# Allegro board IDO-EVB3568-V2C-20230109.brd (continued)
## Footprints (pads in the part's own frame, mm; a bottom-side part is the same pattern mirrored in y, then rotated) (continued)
M_MINIPCIE_SOCKET_CK
  round 1.143 hole 1.143 unplated: (-12.499,0)
  round 1.651 hole 1.651 unplated: (12.499,0)
  rect 0.508x2.032 smd: 1(11.801,4.1) 2(11.399,-4.1) 3(11.001,4.1) 4(10.599,-4.1) 5(10.201,4.1) 6(9.799,-4.1) 7(9.4,4.1) 8(8.999,-4.1) 9(8.6,4.1) 10(8.199,-4.1) 11(7.8,4.1) 12(7.399,-4.1) 13(7,4.1) 14(6.599,-4.1) 15(6.2,4.1) 16(5.801,-4.1) 17(2.2,4.1) 18(1.801,-4.1) 19(1.399,4.1) 20(1.001,-4.1) 21(0.599,4.1) 22(0.201,-4.1) 23(-0.201,4.1) 24(-0.599,-4.1) 25(-1.001,4.1) 26(-1.399,-4.1) 27(-1.801,4.1) 28(-2.2,-4.1) 29(-2.601,4.1) 30(-3,-4.1) 31(-3.401,4.1) 32(-3.8,-4.1) 33(-4.201,4.1) 34(-4.6,-4.1) 35(-4.999,4.1) 36(-5.4,-4.1) 37(-5.801,4.1) 38(-6.2,-4.1) 39(-6.599,4.1) 40(-7,-4.1) 41(-7.399,4.1) 42(-7.8,-4.1) 43(-8.199,4.1) 44(-8.6,-4.1) 45(-8.999,4.1) 46(-9.4,-4.1) 47(-9.799,4.1) 48(-10.201,-4.1) 49(-10.599,4.1) 50(-11.001,-4.1) 51(-11.399,4.1) 52(-11.801,-4.1)
  rect 2.413x3.302 smd: 55(-14.651,3.5) 56(14.651,3.5)
MTG370_600_VIA
  round 0.95 hole 0.3: (-2.425,0) (-1.715,1.715) (-1.715,-1.715) (0,2.425) (0,-2.425) (1.715,1.715) (1.715,-1.715) (2.425,0) (2.425,0)
  round 6 hole 3.7: 1(0,0)
MTG430_620_SMTSO_M3
  round 6.2 hole 4.3: 1(0,0)
MX125T-S-2A
  rect 0.635x1.6 smd: 1(-0.625,0) 2(0.625,0)
  rect 2.134x3.048 smd: 3(-3.175,-2.9) 4(3.175,-2.9)
MX125T-S-3A
  rect 0.635x1.6 smd: 1(-1.25,0) 2(0,0) 3(1.25,0)
  rect 2.134x3.048 smd: 4(-3.8,-2.9) 5(3.8,-2.9)
PB-SIDE-S-3_5X4_5
  round 0.6 hole 0.6 unplated: (-0.851,0) (0.851,0)
  rect 0.9x1.2 smd: 1(2.301,0) 2(-2.301,0)
  rect 1.15x1.3 smd: 3(1.675,1.55) 4(-1.675,1.55)
PH200-2A
  rect 1.2x1.2 hole 0.8: 1(1,0)
  round 1.2 hole 0.8: 2(-1,0)
PH200-4A
  rect 1.2x1.2 hole 0.8: 1(3,0)
  round 1.2 hole 0.8: 2(1,0) 3(-1,0) 4(-3,0)
PH200-6A
  rect 1.2x1.2 hole 0.8: 1(5,0)
  round 1.2 hole 0.8: 2(3,0) 3(1,0) 4(-1,0) 5(-3,0) 6(-5,0)
PH200-6AW
  rect 1.2x1.2 hole 0.8: 1(5,0)
  round 1.2 hole 0.8: 2(3,0) 3(1,0) 4(-1,0) 5(-3,0) 6(-5,0)
PJ-326A-3P
  round 1 hole 1: (-0.5,2.901) (6.5,2.901)
  rect 2.2x2.2 smd: 1(0,0) 2(3,5.801)
  rect 2.4x2.4 smd: 3(9.7,2.901)
QFN-40_5X5X04P
  rect 0.7x0.2 smd: 1(-2.35,1.8) 2(-2.35,1.4) 3(-2.35,1) 4(-2.35,0.6) 5(-2.35,0.2) 6(-2.35,-0.2) 7(-2.35,-0.6) 8(-2.35,-1) 9(-2.35,-1.4) 10(-2.35,-1.8) 21(2.35,-1.8) 22(2.35,-1.4) 23(2.35,-1) 24(2.35,-0.6) 25(2.35,-0.2) 26(2.35,0.2) 27(2.35,0.6) 28(2.35,1) 29(2.35,1.4) 30(2.35,1.8)
  rect 0.2x0.7 smd: 11(-1.8,-2.35) 12(-1.4,-2.35) 13(-1,-2.35) 14(-0.6,-2.35) 15(-0.2,-2.35) 16(0.2,-2.35) 17(0.6,-2.35) 18(1,-2.35) 19(1.4,-2.35) 20(1.8,-2.35) 31(1.8,2.35) 32(1.4,2.35) 33(1,2.35) 34(0.6,2.35) 35(0.2,2.35) 36(-0.2,2.35) 37(-0.6,2.35) 38(-1,2.35) 39(-1.4,2.35) 40(-1.8,2.35)
  rect 3.2x3.2 smd: 41(0,0)
R0402
  rect 0.55x0.55 smd: 1(-0.45,0) 2(0.45,0)
R0603
  rect 0.65x0.8 smd: 1(-0.725,0) 2(0.725,0)
R0805
  rect 1x1.2 smd: 1(-1,0) 2(1,0)
RJ45-TH_HR911130A
  round 2.997 hole 3.251 unplated: (-5.715,0) (5.715,0)
  round 1.524 hole 0.889: 1(5.715,-8.89) 2(4.445,-6.35) 3(3.175,-8.89) 4(1.905,-6.35) 5(0.635,-8.89) 6(-0.635,-6.35) 7(-1.905,-8.89) 8(-3.175,-6.35) 9(-4.445,-8.89) 10(-5.715,-6.35)
  round 1.651 hole 1.016: 11(6.624,4.9) 12(4.084,4.9) 13(-4.084,4.9) 14(-6.624,4.9)
  round 2.54 hole 1.651: SH1(-7.846,-3.051) SH2(7.846,-3.051)
RN_0402X4
  rect 0.5x0.399 smd: 1(-0.5,0.8) 4(-0.5,-0.8) 5(0.5,-0.8) 8(0.5,0.8)
  rect 0.5x0.3 smd: 2(-0.5,0.25) 3(-0.5,-0.25) 6(0.5,-0.25) 7(0.5,0.25)
SIM-91288-021
  rect 1.829x1.397 smd: C1(-0.351,12.319) C2(-0.351,9.779) C3(-0.351,7.239) C5(-23.322,12.319) C6(-23.322,9.779) C7(-23.322,7.239) CD1(-0.351,-0.051) CD2(-23.322,-0.051)
SMA_DO-214AC
  rect 1.85x1.45 smd: A(1.95,0) C(-1.95,0)
SMAF
  rect 1.43x1.53 smd: A(-1.84,0) C(1.84,0)
SMD1812
  rect 2.032x3.302 smd: 1(-2.159,0) 2(2.159,0)
SOD123
  rect 0.8x0.75 smd: A(1.7,0) C(-1.7,0)
SOD323
  rect 0.9x0.5 smd: A(1.3,0) C(-1.3,0)
SOD523
  rect 0.65x0.5 smd: A(0.9,0) C(-0.9,0)
SOD-123F
  rect 0.94x0.95 smd: A(-1.45,0) C(1.45,0)
SOP16-P127-390X990
  rect 1.905x0.635 smd: 1(0,0) 2(0,-1.27) 3(0,-2.54) 4(0,-3.81) 5(0,-5.08) 6(0,-6.35) 7(0,-7.62) 8(0,-8.89) 9(6.096,-8.89) 10(6.096,-7.62) 11(6.096,-6.35) 12(6.096,-5.08) 13(6.096,-3.81) 14(6.096,-2.54) 15(6.096,-1.27) 16(6.096,0)
SOT23
  rect 1.05x0.65 smd: 1(-1.15,0.95) 2(-1.15,-0.95) 3(1.15,0)
SOT23-5
  rect 1.1x0.6 smd: 1(-1.35,0.95) 2(-1.35,0) 3(-1.35,-0.95) 4(1.35,-0.95) 5(1.35,0.95)
SOT23-6
  rect 1.05x0.6 smd: 1(-1.35,0.95) 2(-1.35,0) 3(-1.35,-0.95) 4(1.35,-0.95) 5(1.35,0) 6(1.35,0.95)
SOT353
  rect 0.95x0.4 smd: 1(-1.1,0.65) 2(-1.1,0) 3(-1.1,-0.65) 4(1.1,-0.65) 5(1.1,0.65)
SOT523
  rect 0.85x0.3 smd: 1(-0.8,0.5) 2(-0.8,-0.5) 3(0.8,0)
SOT563
  rect 0.47x0.26 smd: 1(-0.74,0.5) 2(-0.74,0) 3(-0.74,-0.5) 4(0.74,-0.5) 5(0.74,0) 6(0.74,0.5)
TF-01A
  round 1 hole 1: (-7.2,-10.5) (0.8,-10.5)
  oval 0.7x2.3 smd: 1(0,0.2) 2(-1.1,0.2) 3(-2.2,0.2) 4(-3.3,0.2) 5(-4.4,0.2) 6(-5.5,0.2) 7(-6.6,0.2) 8(-7.7,0.2) 9(-8.8,0.2)
  rect 1.2x1.4 smd: 10(-10,-0.5)
  rect 1.6x1.4 smd: 11(4.6,-0.5)
  rect 1.2x2.2 smd: 12(-10,-10.2) 13(5.5,-10.2)
TSSOP-8
  rect 1.905x0.381 smd: 1(-2.1,0.975) 2(-2.1,0.325) 3(-2.1,-0.325) 4(-2.1,-0.975) 5(2.1,-0.975) 6(2.1,-0.325) 7(2.1,0.325) 8(2.1,0.975)
unnamed
  round 1 smd: 1(0,0)
USB-9AF-DIP_2X
  round 1.118 hole 0.711: 1(-3.5,0) 2(-1,0) 3(1,0) 4(3.5,0) 5(4,1.5) 6(2,1.5) 7(0,1.5) 8(-2,1.5) 9(-4,1.5) 10(-3.5,3.2) 11(-1,3.2) 12(1,3.2) 13(3.5,3.2) 14(4,4.7) 15(2,4.7) 16(0,4.7) 17(-2,4.7) 18(-4,4.7)
  round 2.794 hole 2.362: 19(-6.57,3.68) 20(6.57,3.68) 21(6.57,-2) 22(-6.57,-2)
USB_SMD-TYPE-C-16P
  round 0.711 hole 0.711 unplated: (-2.89,3.65) (2.89,3.65)
  rect 0.3x1.25 smd: A1(-3.35,4.75) A4(-2.6,4.75) A5(-1.25,4.75) A6(-0.25,4.75) A7(0.25,4.75) A8(-1.75,4.75) A9(2.55,4.75) A12(3.35,4.75) B1(3.05,4.75) B4(2.25,4.75) B5(1.75,4.75) B6(0.75,4.75) B7(-0.75,4.75) B8(1.25,4.75) B9(-2.3,4.75) B12(-3.05,4.75)
  oval 1.2x2.5 hole 0.6x1.8: H1(-4.32,4.15) H2(4.32,4.15)
  oval 1x2 hole 0.6x1.5: H3(-4.32,0) H4(4.32,0)
V0402
  rect 0.57x0.62 smd: 1(-0.48,0) 2(0.48,0)
WIFI_44P_12X12
  rect 1.2x0.5 smd: 1(-5.7,4.5) 2(-5.7,3.6) 3(-5.7,2.7) 4(-5.7,1.8) 5(-5.7,0.9) 6(-5.7,0) 7(-5.7,-0.9) 8(-5.7,-1.8) 9(-5.7,-2.7) 10(-5.7,-3.6) 11(-5.7,-4.5) 23(5.7,-4.5) 24(5.7,-3.6) 25(5.7,-2.7) 26(5.7,-1.8) 27(5.7,-0.9) 28(5.7,0) 29(5.7,0.9) 30(5.7,1.8) 31(5.7,2.7) 32(5.7,3.6) 33(5.7,4.5)
  rect 0.5x1.2 smd: 12(-4.5,-5.7) 13(-3.6,-5.7) 14(-2.7,-5.7) 15(-1.8,-5.7) 16(-0.9,-5.7) 17(0,-5.7) 18(0.9,-5.7) 19(1.8,-5.7) 20(2.7,-5.7) 21(3.6,-5.7) 22(4.5,-5.7) 34(4.5,5.7) 35(3.6,5.7) 36(2.7,5.7) 37(1.8,5.7) 38(0.9,5.7) 39(0,5.7) 40(-0.9,5.7) 41(-1.8,5.7) 42(-2.7,5.7) 43(-3.6,5.7) 44(-4.5,5.7)
  round 0.6 smd: 45(-2.7,3.6) 46(-0.9,3.6) 47(0.9,3.6)
XTAL_32X15_2P
  rect 0.85x1.6 smd: 1(-1.25,0) 2(1.25,0)
XTAL_32X25_4P
  rect 1.2x1.3 smd: 1(-0.9,1.2) 2(-0.9,-1.2) 3(0.9,-1.2) 4(0.9,1.2)

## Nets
GND: C3.2 C4.1 C5.1 C6.1 C7.1 C9.1 C10.1 C11.1 C12.1 C14.1 C15.1 C16.1 C18.1 C19.1 C20.1 C21.1 C22.1 C23.1 C25.1 C26.1 C27.1 C28.1 C29.1 C30.1 C31.1 C32.1 C33.2 C34.2 C35.1 C36.2 C37.2 C38.2 C40.2 C42.2 C43.2 C44.1 C45.1 C46.2 C47.2 C48.1 C49.1 C50.1 C51.1 C52.2 C53.2 C54.1 C55.1 C56.1 C57.1 C58.1 C59.1 C60.1 C61.1 C62.1 C63.2 C65.1 C66.1 C67.1 C68.1 C71.1 C73.2 C74.2 C76.2 C77.2 C78.1 C79.1 C80.1 C81.1 C82.1 C83.1 C84.1 C85.1 C86.1 C87.1 C88.1 C89.1 C90.1 C91.1 C93.1 C94.1 C95.1 C96.1 C97.1 C98.1 C99.1 C100.1 C101.1 C102.1 C103.1 C104.1 C105.1 C106.1 C107.1 C109.1 C110.1 C111.1 C112.1 C114.2 C115.1 C116.1 C117.1 C118.1 C119.1 C120.1 C121.1 C122.1 C123.1 C125.1 C126.1 C127.1 C128.1 C129.1 C130.1 C131.1 C132.1 C133.1 C134.1 C135.1 C136.1 C137.1 C138.1 C139.1 C140.1 C141.1 C142.1 C143.1 C144.1 C145.1 C146.1 C147.1 C148.1 C149.1 C150.1 C151.1 C152.1 C153.1 C154.1 C155.1 C156.1 C157.1 C158.1 C159.1 C160.1 C161.1 C162.1 C163.1 C164.2 C165.1 C166.1 C167.1 C168.2 C169.1 C170.1 C171.1 C172.1 C173.1 C174.1 C175.1 C176.2 C177.2 C179.1 C180.1 C181.1 C182.1 C183.2 C184.2 C185.2 C186.2 C188.2 C190.1 C191.1 C192.1 C193.1 C194.1 C195.1 C196.1 C197.1 C198.1 C199.1 C200.1 C201.1 C202.1 C203.1 C204.1 C205.1 C206.1 C208.1 C209.1 C214.1 C215.1 C216.1 C217.1 C218.1 C219.1 C220.1 C221.1 C222.1 C243.1 C244.1 C245.1 C247.1 C248.1 C249.1 C250.1 C251.1 C252.1 C253.1 C254.1 C255.1 C258.1 C259.1 C260.1 C261.1 D2.1(I/O2) D3.3 D3.8 D4.3 D4.8 D5.1(I/O2) D6.1(I/O2) D7.1(I/O2) D8.1(I/O2) D9.1(I/O2) D10.1(I/O2) D12.1(I/O2) D14.3 D14.8 D15.2(I/O1) D16.2(I/O1) D17.3 D17.8 D18.1(I/O2) D19.1(I/O2) D20.1(I/O2) D21.1(I/O2) D22.1(I/O2) D23.1(I/O2) D24.1(I/O2) D25.1(I/O2) D26.1(I/O2) D27.1(I/O2) D28.1(I/O2) D29.1(I/O2) D30.1(I/O2) D31.1(I/O2) D32.1(I/O2) D33.1(I/O2) D34.3 D34.8 D35.3 D35.8 D36.2(I/O1) D37.3 D37.8 D38.2(I/O1) D40.3 D40.8 D41.3 D41.8 D44.2(I/O1) D45.2(I/O1) D46.2(I/O1) D47.2(I/O1) D48.3 D48.8 D49.3 D49.8 D51.3 D51.8 D52.2(I/O1) D53.2(I/O1) D64.2(I/O1) D65.2(I/O1) D71.2(I/O1) D72.2(I/O1) D73.2(I/O1) D74.2(I/O1) D75.2(I/O1) D76.3 D76.8 D77.3 D77.8 D79.2(I/O1) D80.2(I/O1) D81.2 D82.2 D83.2 D84.2 D96.2(I/O1) D97.1(I/O2) D98.3 D98.8 D99.3 D99.8 D100.2(I/O1) D101.2(I/O1) D102.3 D102.8 D103.3 D103.8 D104.3 D104.8 D105.2(I/O1) D106.2(I/O1) D107.3 D107.8 H1.1 H2.1 J2.15(GND1) J2.30(GND2) J2.31(GND3) J2.51(GND4) J2.56(GND5) J2.69(GND6) J2.84(GND7) J2.95(GND8) J2.106(GND9) J2.121(GND10) J2.145(GND11) J2.151(GND12) J2.158(GND13) J2.165(GND14) J2.180(GND15) J2.194(GND16) J2.195(GND17) J2.214(GND18) J2.217(GND19) J2.240(GND20) J2.254(GND21) J2.256(GND22) J2.258(GND23) J2.260(GND24) J2.N1 J2.N2 J2.N3 J2.N4 J3.6(VSS) J3.10(G1) J3.11(G2) J3.12(G3) J3.13(G4) J4.3 J4.4 J4.5 J5.A1(GND1) J5.A12(GND2) J5.B1(GND3) J5.B12(GND4) J5.H1(GND5) J5.H2(GND6) J5.H3(GND7) J5.H4(GND8) J6.4(GND1) J6.7(GND2) J6.13(GND3) J6.16(GND4) J6.19(SHELL1) J6.20(SHELL2) J6.21(SHELL3) J6.22(SHELL4) J7.4 J8.4 J9.4 J11.2 J13.11 J13.16 J13.18 J13.19 J13.22 J13.25 J13.28 J13.31 J13.34 J13.37 J13.41 J13.42 J14.2 J14.5 J14.8 J14.11 J14.14 J14.17 J14.20 J14.21 J14.22 J14.23 J15.11 J15.16 J15.18 J15.19 J15.22 J15.25 J15.28 J15.31 J15.34 J15.37 J15.41 J15.42 J16.5 J16.6 J16.13 J16.14 J19.10 J19.13 J19.16 J19.19 J19.22 J19.25 J19.26 J20.10 J20.13 J20.16 J20.19 J20.22 J20.25 J20.26 J21.1(GND1) J21.3(GND2) J21.4(GND3) J22.10(GND) J23.10(GND) J24.5 J24.6 J24.24 J24.33 J24.34 J25.2 J25.3 J25.4 J26.4(GND#4) J26.9(GND#9) J26.15(GND#15) J26.18(GND#18) J26.21(GND#21) J26.26(GND#26) J26.27(GND#27) J26.29(GND#29) J26.34(GND#34) J26.35(GND#35) J26.37(GND#37) J26.40(GND#40) J26.43(GND#43) J26.50(GND#50) J26.55(GND#55) J26.56(GND#56) J27.1(GND#1) J27.3(GND#3) J27.9(GND#9) J27.15(GND#15) J27.21(GND#21) J27.27(GND#27) J27.33(GND#33) J27.39(GND#39) J27.45(GND#45) J27.51(GND#51) J27.57(GND#57) J27.71(GND#71) J27.73(GND#73) J27.75(GND#75) J27.G1(EHT1) J27.G2(EHT2) J27.G3(G4) J27.G4(G3) J28.4 J28.13 J28.14 J31.6 J31.7 J31.8 L1.3 LED1.2 LED1.4 Q1.2(SOURCE) Q2.2(SOURCE) Q8.2(SOURCE) Q13.2(SOURCE) Q14.2(SOURCE) Q15.2(SOURCE) R2.2 R5.1 R6.1 R9.1 R12.1 R16.1 R28.1 R33.1 R36.1 R41.1 R45.1 R51.1 R60.1 R72.1 R73.2 R79.1 R81.2 R100.1 R101.1 R102.1 R108.1 R118.1 R119.1 R120.1 R173.1 R176.1 R179.1 R201.2 R208.1 R213.2 R219.1 R225.1 R229.1 R233.1 R235.1 R237.1 R239.1 R241.1 R242.1 R245.1 R268.2 R271.1 R273.1 R277.1 R281.1 R284.1 R286.1 R287.1 R289.1 R290.1 R293.1 R345.1 R385.2 R419.1 R421.1 SIM1.C5(GND) SW1.1 SW1.2 SW1.4 SW2.1 SW2.2 SW2.4 U1.3(GND) U2.3(GND) U3.2(GND) U4.2(GND) U5.2(GND) U6.2(GND) U7.2(GND) U8.6(VSS) U8.10(VS_PLL) U8.16(VSS_1) U8.22(VSS-2) U8.25(VS_A) U8.33(VSS_3) U8.37(DIS_REG) U8.40(TEST) U9.2(GND) U10.2(GND) U11.2(PGND1) U11.11(GND1) U11.15(PGND2) U12.2(GND) U13.2(GND) U14.1(O\E\) U14.3(GND) U15.2(GND) U16.2(GND) U17.2(GND) U18.1(GND1) U18.3(GND2) U18.20(GND3) U18.31(GND4) U18.33(GND5) U18.36(GND6) U19.41(E_PAD) U20.41(E_PAD) U21.4(VSS) U22.2(GND) U25.1(O\E\) U25.3(GND) XT1.2 XT1.4 XT2.2 XT2.4 XT3.2 XT3.4 XT4.2 XT4.4
GND_EARTH: C261.2 HOLE1.1 HOLE2.1 HOLE3.1 HOLE4.1 J22.SH1 J22.SH2 J23.SH1 J23.SH2 R419.2
GND_IN: C2.1 C256.1 C257.1 D1.C(I/O1) J1.2 J1.3 J18.1 J18.2 J30.1 J30.2 J32.1 J32.2 L1.2 R2.1
VBAT_RTC: D70.A J25.1
VBAT_WL_1T1R: C118.2 C119.2 C125.2 Q10.3(DRAIN) R202.2 U18.9(VBAT)
VBUSM: R74.1 U8.35(VBUSM)
VCC1V5_DVP: C100.2 C106.2 C107.2 C108.1 C254.2 J19.3 J20.3 R175.2 U16.5(VOUT)
VCC1V8_DVP: C102.2 C103.2 C104.2 C255.2 J19.4 J20.4 Q16.1(GATE) Q17.1(GATE) R156.2 R161.2 R162.2 R166.2 R172.2 U15.5(VOUT)
VCC2V8_DVP: C98.2 C110.2 C111.2 C253.2 J19.1 J19.2 J20.1 J20.2 R177.2 U17.5(VOUT)
VCC3V3_PHY0: C148.2 C149.2 C150.2 C151.2 C152.2 R211.2 R226.2 R230.2 R258.2 U19.11(AVDD33#11) U19.29(DVDD33) U19.40(AVDD33#40)
VCC3V3_PHY1: C172.2 C173.2 C174.2 C175.2 C176.1 R274.2 R278.2 R306.2 U20.11(AVDD33#11) U20.29(DVDD33) U20.40(AVDD33#40)
VCC3V3_SD: C31.2 D2.2(I/O1) J2.210(VCC3V3_SD_OUT) J3.4(VDD)
VCC5V0_M: C26.2 C27.2 C28.2 C29.2 J2.253(VCC5V0_SYS1) J2.255(VCC5V0_SYS2) J2.257(VCC5V0_SYS3) J2.259(VCC5V0_SYS4) R17.2
VCC5V0_USB1: C42.1 D19.2(I/O1) J7.1 U7.1(VOUT)
VCC5V0_USB2: C46.1 D21.2(I/O1) J8.1 U9.1(VOUT)
VCC5V0_USB3: C52.1 D24.2(I/O1) J9.1 U10.1(VOUT)
VCC5V0_USB_HOST1: C38.1 D16.1(I/O2) J6.10(VBUS2) U6.1(VOUT)
VCC5V0_USB_HOST2: C36.1 D15.1(I/O2) J6.1(VBUS1) U5.1(VOUT)
VCC5V0_USB_OTG0: C32.2 C34.1 D7.2(I/O1) J5.A4(VBUS_1) J5.A9(VBUS_2) J5.B4(VBUS_3) J5.B9(VBUS_4) R27.1 U4.1(VOUT)
VCC5V_HDMI_TX: C85.2 D43.C J14.18
VCC5V_SPK: C249.2 C250.2 C251.2 C252.2 R86.2 U11.4(PVDD1) U11.13(PVDD2)
VCC5V_SYS: C8.2 C9.2 C10.2 C11.2 D42.A D43.A L2.2 Q5.1(GATE) R4.2 R7.2 R17.1
VCC12V_DCIN: C256.2 C257.2 F2.1 J1.4 J17.1 J18.5 J18.6 J29.1 J30.5 J30.6 J32.3 J32.4
VCC_1V8: J2.237(VCC_1V8_OUT) Q19.1(GATE) R30.2 R154.2 R155.2 R200.1 R250.1 R298.1 R398.1 R399.1 R408.1 R413.1
VCC_1V8_HUB: C50.2 C60.2 C61.2 C62.2 U8.3(VD18_1) U8.9(VD_PLL) U8.26(VREG18) U8.29(VD18)
VCC_3V3: J2.245(VCC_3V3_OUT) R14.1
VCC_3V3_HUB: C54.2 C55.2 C56.2 C57.2 C58.2 C59.2 R54.2 R55.2 R58.2 R59.1 R61.2 R65.1 R66.2 R76.2 U8.13(VDD33_1) U8.19(VDD33_2) U8.27(VD3_IN) U8.32(VDD33_3) U8.41(VDD33_4)
VCC_3V8: C190.2 C191.2 C192.2 C193.2 C194.2 C195.2 C196.2 C197.2 C198.2 C199.2 C200.2 C201.2 C202.2 C203.2 C204.2 C207.2 C208.2 C209.2 J26.2(VCC3V3#2) J26.24(NC3) J26.39(VCC3V3#39) J26.41(VCC3V3#41) J26.52(VCC3V3#52) L24.2 R342.2 R343.2
VCC_5V: C17.2 C18.2 C19.2 C20.2 C22.2 C23.2 C33.1 C37.1 C40.1 C43.1 C47.1 C53.1 C82.2 C83.2 C88.2 C89.2 C94.2 C177.1 C205.2 C206.2 C244.2 C248.2 J17.3 J24.35 J24.36 J29.3 L3.2 L15.1 L20.1 Q7.1(GATE) Q11.1(GATE) R11.2 R86.1 R133.1 R388.1 U3.4(VIN) U4.5(IN) U5.5(IN) U6.5(IN) U7.5(IN) U9.5(IN) U10.5(IN) U12.6(VIN) U13.6(VIN) U14.5(VCC) U22.4(VIN) U25.5(VCC)
VCC_12V: C3.1 C4.2 C5.2 C6.2 C7.2 C14.2 C15.2 C16.2 L1.4 R1.2 R3.2 U1.1(IN) U2.1(IN)
VCC_EDP_OUT: C245.2 C246.2 J29.2 J29.4 J29.6 Q12.2(SOURCE) R391.2
VCC_EDP_OUT_: C247.2 J28.1 J28.2 Q12.3(DRAIN)
VCC_LEDA_TX0: C86.2 C87.2 D50.C J15.1 J15.2 U13.5(OVP)
VCC_LEDA_TX1: C81.2 C84.2 D39.C J13.1 J13.2 U12.5(OVP)
VCC_LEDK_TX0: J15.9 J15.10 R117.1 R119.2 R120.2
VCC_LEDK_TX1: J13.9 J13.10 R99.1 R101.2 R102.2
VCC_LVDS_OUT: C91.2 C92.2 J17.2 J17.4 J17.6 Q6.2(SOURCE) R134.2
VCC_LVDS_OUT_: C93.2 J16.1 J16.2 J16.3 Q6.3(DRAIN)
VCCA_CODEC: C67.2 C68.2 R85.2 U11.6(VDD1) U11.9(VDD2)
VCCIO_PHY0: C144.2 C145.2 C146.2 R236.2 R238.2 R240.2 R243.2 R246.2 R249.2 R250.2 U19.28(DVDD_RG)
VCCIO_PHY1: C168.1 C169.2 C170.2 R283.2 R285.2 R288.2 R291.2 R294.2 R297.2 R298.2 U20.28(DVDD_RG)
VCCIO_WL: C120.2 C121.2 C122.2 R180.1 R185.1 R200.2 R204.1 U18.22(VDDIO)
VDD3V3_PCIE30: C214.2 C215.2 C216.2 C217.2 C218.2 C219.2 C220.2 C221.2 C222.2 J27.2(3.3V#2) J27.4(3.3V#4) J27.12(3.3V#12) J27.14(3.3V#14) J27.16(3.3V#16) J27.18(3.3V#18) J27.70(3.3V#70) J27.72(3.3V#72) J27.74(3.3V#74) R359.2
VDD10_PHY0: C136.2 C137.2 C138.2 C139.2 C140.2 C141.2 L22.2 U19.3(AVDD10#3) U19.8(AVDD10#8) U19.21(DVDD10) U19.38(AVDD10#38)
VDD10_PHY1: C160.2 C161.2 C162.2 C163.2 C164.1 C165.2 L23.2 U20.3(AVDD10#3) U20.8(AVDD10#8) U20.21(DVDD10) U20.38(AVDD10#38)
VDD_3V3: C21.2 C24.2 C25.2 C79.2 C101.2 C105.2 C109.2 C123.2 C124.2 C243.2 C260.2 D69.A J13.38 J13.39 J15.38 J15.39 J17.5 J28.19 J29.5 J31.1 L4.2 Q3.1(GATE) Q4.1(GATE) Q10.2(SOURCE) R10.1 R15.2 R37.2 R74.2 R76.1 R80.1 R85.1 R92.2 R93.2 R98.1 R103.1 R105.1 R109.2 R111.2 R112.2 R121.1 R132.1 R202.1 R203.2 R258.1 R267.2 R306.1 R326.2 R327.2 R359.1 R384.1 R387.1 R400.1 R401.1 R409.1 R415.1 U15.1(VIN) U16.1(VIN) U17.1(VIN)
VDD_RTC: C181.2 D69.C D70.C U21.8(VDD)
4G_PWREN_H_GPIO0_D5: J2.11(GPIO0_D5_D/SARADC_VIN6) R344.1
4G_RESET_L_GPIO0_D4: J2.9(GPIO0_D4_D/SARADC_VIN5) R337.2
5G_SSRXN: J26.23(UART1_CTS) R423.2
5G_SSRXP: J26.25(UART1_RFR) R422.2
5G_SSTXN: C187.2 J26.31(UART1_DTR)
5G_SSTXP: C189.2 J26.33(UART1_DCD)
BT_REG_ON_H_GPIO1_D4: J2.18(FSPI_D3/FLASH_CS1N/GPIO1_D4_U) R209.1
BT_WAKE_HOST: R199.2 U18.7(BT_HOST_WAKE)
BT_WAKE_HOST_H_GPIO2_C1: J2.228(I2S2_MCLK_M0/ETH0_REFCLKO_25M/U) R199.1
CAM0_PDN_H_GPIO1_D0: J2.10(FSPI_CLK/FLASH_ALE/GPIO1_D0_D) R150.1
CAM0_RST_L__GPIO1_D1: J2.12(FSPI_D0/FLASH_RDY/GPIO1_D1_U) R151.1
CAM1_PDN_H_GPIO1_D2: J2.14(FSPI_D1/FLASH_RDN/GPIO1_D2_U) R164.1
CAM1_RST_L_GPIO1_C7: J2.16(FSPI_D2/FLASH_WPN/GPIO1_C7_D) R165.1
CAM_CLKOUT0: J2.108(REFCLK_OUT/GPIO0_A0_D) R163.1
CAMERA_PWREN: R416.2 U15.3(EN) U16.3(EN) U17.3(EN)
CAMERA_PWREN_GPIO4_D2: J2.13(GPIO4_D2_D/SARADC_VIN7) R416.1
CAN1_RX: J24.18 R310.5
CAN1_RX_M0: J2.154(I2C3_SDA_M0/UART3_RX_M0/CAN1_RX) R310.4
CAN1_TX: J24.17 R310.6
CAN1_TX_M0: J2.156(I2C3_SCL_M0/UART3_TX_M0/CAN1_TX) R310.3
CAN2_RX: D90.C J24.20 R401.2
CAN2_RX_M0: D90.A J2.44(I2C2_SDA_M1/EBC_GDSP/CAN2_RX_M0) R398.2
CAN2_TX: J24.19 Q19.3(DRAIN) R400.2
CAN2_TX_M0: J2.46(I2C2_SCL_M1/EBC_SDSHR/CAN2_TX_M) Q19.2(SOURCE) R399.2
CIF_CLK0: C95.2 D102.5 D102.6 J19.9 R149.2
CIF_CLK1: C97.2 D103.5 D103.6 J20.9 R163.2 R421.2
CIF_CLKOUT_SOC: J2.52(CIF_CLKOUT/EBC_GDCLK/PWM11_IR_M) R149.1
CIF_PDN0: D102.1 D102.10 J19.6 R150.2
CIF_PDN1: D103.1 D103.10 J20.6 R164.2
CIF_RST0: C96.2 J19.5 R151.2 R156.1
CIF_RST1: C99.2 J20.5 R165.2 R166.1
CLK_32K_OUT: J27.68(SUSCLK(32KHZ)(I)(3.3V)) R352.2
CLK_32K_OUT_GPIO0_B0: J2.112(CLK32K_IN/CLK32K_OUT0/PCIE30X2_) R352.1
DM1_: D18.2(I/O1) J7.2 L8.3 R52.2
DM2_: D23.2(I/O1) J8.2 L9.3 R64.2
DM3_: D25.2(I/O1) J9.2 L10.3 R75.2
DM4: J26.36(USB_D-) R340.1
DM_1: D65.1(I/O2) J24.31 R307.2
DP1_: D20.2(I/O1) J7.3 L8.4 R56.2
DP2_: D22.2(I/O1) J8.3 L9.4 R67.2
DP3_: D26.2(I/O1) J9.3 L10.4 R78.2
DP4: J26.38(USB_D+) R341.1
DP_1: D64.1(I/O2) J24.32 R308.2
DRV: U8.42(DRV)
EDP_EN_H_GPIO0_C5: J2.130(PWM6/SPI0_MISO_M0/PCIE30X2_WAKE) R393.2
EDP_ON_: J30.4 Q11.2(SOURCE) R388.2 R389.2
EDP_ON_GPIO0_C3: J2.126(PWM4/VOP_PWM_M0/PCIE30X1_PERSTN) Q11.3(DRAIN) R387.2 R389.1
EDP_PWM7: J2.132(PWM7_IR/SPI0_CS0_M0/PCIE30X2_PE) R390.1 U25.2(A)
EDP_PWM7_: J30.3 R390.2 U25.4(Y)
EDP_TX_AUXN: C235.2 J2.197(EDP_TX_AUXN)
EDP_TX_AUXN_: C235.1 D77.4 D77.7 J28.15 R384.2
EDP_TX_AUXP: C236.2 J2.199(EDP_TX_AUXP)
EDP_TX_AUXP_: C236.1 D77.5 D77.6 J28.16 R385.1
EDP_TX_D0N: C241.2 J2.213(EDP_TX_D0N)
EDP_TX_D0N_: C241.1 D76.1 D76.10 J28.7
EDP_TX_D0P: C242.2 J2.215(EDP_TX_D0P)
EDP_TX_D0P_: C242.1 D76.2 D76.9 J28.8
EDP_TX_D1N: C239.2 J2.209(EDP_TX_D1N)
EDP_TX_D1N_: C239.1 D76.4 D76.7 J28.9
EDP_TX_D1P: C240.2 J2.211(EDP_TX_D1P)
EDP_TX_D1P_: C240.1 D76.5 D76.6 J28.10
EDP_TX_D2N: C237.2 J2.205(EDP_TX_D2N)
EDP_TX_D2N_: C237.1 D77.1 D77.10 J28.11
EDP_TX_D2P: C238.2 J2.207(EDP_TX_D2P)
EDP_TX_D2P_: C238.1 D77.2 D77.9 J28.12
EDP_TX_D3N: C233.2 J2.201(EDP_TX_D3N)
EDP_TX_D3N_: C233.1 D80.1(I/O2) J28.17
EDP_TX_D3P: C234.2 J2.203(EDP_TX_D3P)
EDP_TX_D3P_: C234.1 D79.1(I/O2) J28.18
EXT_EN: J2.249(EXT_EN) R13.1
FE1_1_DM0: R71.1 U8.30(DMU)
FE1_1_DM1: L8.2 R52.1 R307.1 U8.23(DM1)
FE1_1_DM2: L9.2 R64.1 U8.20(DM2)
FE1_1_DM3: L10.2 R75.1 U8.17(DM3)
FE1_1_DM4: R340.2 U8.14(DM4)
FE1_1_DP0: R69.1 U8.31(DPU)
FE1_1_DP1: L8.1 R56.1 R308.1 U8.24(DP1)
FE1_1_DP2: L9.1 R67.1 U8.21(DP2)
FE1_1_DP3: L10.1 R78.1 U8.18(DP3)
FE1_1_DP4: R341.2 U8.15(DP4)
FE1_1_XIN: C49.2 R68.1 U8.12(XIN) XT1.1
FE1_1_XOUT: C51.2 R68.2 U8.11(XOUT) XT1.3
GMAC0_MCLKINOUT: C131.2 J2.230(I2S2_SCLK_TX_M0/GMAC0_MCLKINOUT) R216.1 R219.2
GMAC0_MDC: J2.232(I2S2_LRCK_TX_M0/GMAC0_MDC/UART9) U19.13(MDC)
GMAC0_MDIO: J2.234(I2S2_SDO_M0/GMAC0_MDIO/UART9_CT) R249.1 U19.14(MDIO)
GMAC0_RSTN_GPIO2_D5: J2.77(LCDC_D5/VOP_BT656_D5_M0/SPI2_CS) R248.1
GMAC0_RXCLK: C147.2 J2.223(SDMMC1_D2/GMAC0_RXCLK/UART7_RX_) R256.2
GMAC0_RXD0: J2.222(GMAC0_RXD0/UART1_CTSN_M0/SPI1_M) R252.2
GMAC0_RXD1: J2.224(I2S2_SCLK_RX_M0/GMAC0_RXD1/UART) R253.2
GMAC0_RXD2: J2.219(SDMMC1_D0/GMAC0_RXD2/UART6_RX_M) R254.2
GMAC0_RXD3: J2.221(SDMMC1_D1/GMAC0_RXD3/UART6_TX_M) R255.2
GMAC0_RXDV_CRS: J2.226(I2S2_LRCK_RX_M0/GMAC0_RXDV_CRS/) R257.2
GMAC0_TXCLK: C134.2 J2.229(SDMMC1_CLK/GMAC0_TXCLK/UART9_TX) R234.1
GMAC0_TXCLK_: C135.2 R234.2 U19.20(TXC)
GMAC0_TXD0: J2.216(GMAC0_TXD0/UART1_RX_M0/GPIO2_B3) R224.1
GMAC0_TXD0_: R224.2 U19.18(TXD0)
GMAC0_TXD1: J2.218(GMAC0_TXD1/UART1_TX_M0/GPIO2_B4) R227.1
GMAC0_TXD1_: R227.2 U19.17(TXD1)
GMAC0_TXD2: J2.225(SDMMC1_D3/GMAC0_TXD2/UART7_TX_M) R228.1
GMAC0_TXD2_: R228.2 U19.16(TXD2)
GMAC0_TXD3: J2.227(SDMMC1_CMD/GMAC0_TXD3/UART9_RX_) R231.1
GMAC0_TXD3_: R231.2 U19.15(TXD3)
GMAC0_TXEN: J2.220(GMAC0_TXEN/UART1_RTSN_M0/SPI1_C) R232.1
GMAC0_TXEN_: R232.2 U19.19(TXCTL)
GMAC1_MCLKINOUT_M1: C155.2 J2.54(CIF_CLKIN/EBC_SDCLK/GMAC1_MCLKI) R270.1 R271.2
GMAC1_MDC_M1: J2.48(CIF_HREF/EBC_SDLE/GMAC1_MDC_M1/) U20.13(MDC)
GMAC1_MDIO_M1: J2.50(CIF_VSYNC/EBC_SDOE/GMAC1_MDIO_M) R297.1 U20.14(MDIO)
GMAC1_RSTN_GPIO2_D7: J2.73(LCDC_D7/VOP_BT656_D7_M0/SPI2_MI) R296.1
GMAC1_RXCLK_M1: C171.2 J2.45(CIF_D13/EBC_SDDO13/GMAC1_RXCLK_) R304.2
GMAC1_RXD0_M1: J2.34(CAM_CLKOUT0/EBC_SDCE1/GMAC1_RXD) R300.2
GMAC1_RXD1_M1: J2.36(CAM_CLKOUT1/EBC_SDCE2/GMAC1_RXD) R301.2
GMAC1_RXD2_M1: J2.41(CIF_D11/EBC_SDDO11/GMAC1_RXD2_M) R302.2
GMAC1_RXD3_M1: J2.43(CIF_D12/EBC_SDDO12/GMAC1_RXD3_M) R303.2
GMAC1_RXDV_CRS_M1: J2.38(ISP_PRELIGHT_TRIG/EBC_SDCE3/GMA) R305.2
GMAC1_TXCLK_M1: C158.2 J2.39(CIF_D10/EBC_SDDO10/GMAC1_TXCLK_) R282.1
GMAC1_TXCLK_M1_: C159.2 R282.2 U20.20(TXC)
GMAC1_TXD0_M1: J2.47(CIF_D14/EBC_SDDO14/GMAC1_TXD0_M) R272.1
GMAC1_TXD0_M1_: R272.2 U20.18(TXD0)
GMAC1_TXD1_M1: J2.49(CIF_D15/EBC_SDDO15/GMAC1_TXD1_M) R275.1
GMAC1_TXD1_M1_: R275.2 U20.17(TXD1)
GMAC1_TXD2_M1: J2.35(CIF_D8/EBC_SDDO8/GMAC1_TXD2_M1/) R276.1
GMAC1_TXD2_M1_: R276.2 U20.16(TXD2)
GMAC1_TXD3_M1: J2.37(CIF_D9/EBC_SDDO9/GMAC1_TXD3_M1/) R279.1
GMAC1_TXD3_M1_: R279.2 U20.15(TXD3)
GMAC1_TXEN_M1: J2.32(ISP_FLASHTRIGOUT/EBC_SDCE0/GMAC) R280.1
GMAC1_TXEN_M1_: R280.2 U20.19(TXCTL)
HDMI_TX_CEC_PORT: D44.1(I/O2) J14.13 Q5.3(DRAIN)
HDMI_TX_CLKN: J2.147(HDMI_TX_CLKN) L19.2
HDMI_TX_CLKN_: D41.5 D41.6 J14.12 L19.3
HDMI_TX_CLKP: J2.149(HDMI_TX_CLKP) L19.1
HDMI_TX_CLKP_: D41.4 D41.7 J14.10 L19.4
HDMI_TX_D0N: J2.155(HDMI_TX_D0N) L18.2
HDMI_TX_D0N_: D41.2 D41.9 J14.9 L18.3
HDMI_TX_D0P: J2.153(HDMI_TX_D0P) L18.1
HDMI_TX_D0P_: D41.1 D41.10 J14.7 L18.4
HDMI_TX_D1N: J2.159(HDMI_TX_D1N) L17.2
HDMI_TX_D1N_: D40.5 D40.6 J14.6 L17.3
HDMI_TX_D1P: J2.157(HDMI_TX_D1P) L17.1
HDMI_TX_D1P_: D40.4 D40.7 J14.4 L17.4
HDMI_TX_D2N: J2.163(HDMI_TX_D2N) L16.2
HDMI_TX_D2N_: D40.2 D40.9 J14.3 L16.3
HDMI_TX_D2P: J2.161(HDMI_TX_D2P) L16.1
HDMI_TX_D2P_: D40.1 D40.10 J14.1($PIN0) L16.4
HDMI_TX_HPD_PORT: D46.1(I/O2) J14.19 R107.2 R108.2
HDMI_TX_HPDIN: J2.143(HDMI_TX_HPDIN) R107.1
HDMI_TXDDC_SCL_PORT: D45.1(I/O2) J14.15 Q3.3(DRAIN) R104.1
HDMI_TXDDC_SDA_PORT: D47.1(I/O2) J14.16 Q4.3(DRAIN) R106.2
HDMITX_CEC_M0: J2.89(HDMITX_CEC_M0/SPI3_CS1_M1/GPIO4) Q5.2(SOURCE) R109.1
HOST_WAKE_BT: R394.2 U18.6(BT_WAKE)
HOST_WAKE_BT_H_GPIO1_D3: J2.20(FSPI_CS0N/FLASH_CS0N/GPIO1_D3_U) R394.1
HP_SNS: J2.244(HP_SNS) J10.1(COM) R81.1
HPL_OUT: C72.2 J2.242(HPL_OUT) R84.1
HPR_OUT: C75.2 J2.246(HPR_OUT) R82.1
HUB_RST: C48.2 R53.2 R66.1 U8.34(XRSTJ)
HUB_RST_GPIO1_A4_D: J2.8(I2S1_SCLK_RX_M0/UART4_RX_M0/PDM) R53.1
I2C1_SCL: J2.146(I2C1_SCL/CAN0_TX_M0/PCIE30X1_BU) R311.2
I2C1_SCL_: J24.22 R311.7
I2C1_SDA: J2.148(I2C1_SDA/CAN0_RX_M0/PCIE20_BUTT) R311.1
I2C1_SDA_: J24.21 R311.8
I2C2_SCL_M0: J2.150(I2C2_SCL_M0/SPI0_CLK_M0/PCIE20_) R111.1 R115.1
I2C2_SDA_M0: J2.152(I2C2_SDA_M0/SPI0_MOSI_M0/PCIE20) R112.1 R116.1
I2C3_SCL_M1: J2.74(LCDC_D20/VOP_BT1120_D11/GMAC1_T) R92.1 R96.1
I2C3_SDA_M1: J2.72(LCDC_D21/VOP_BT1120_D12/GMAC1_T) R93.1 R97.1
I2C4_SCL_M0: J2.42(I2C4_SCL_M0/EBC_GDOE/ETH1_REFCL) R152.1 R155.1
I2C4_SDA_M0: J2.40(I2C4_SDA_M0/EBC_VCOM/GMAC1_RXER) R153.1 R154.1
I2C5_SCL-HDMI: J2.93(HDMITX_SCL/I2C5_SCL_M1/GPIO4_C7) Q3.2(SOURCE) R103.2
I2C5_SCL_M0: J2.78(LCDC_D18/VOP_BT1120_D9/GMAC1_RX) Q17.3(DRAIN) R327.1 R328.2
I2C5_SDA-HDMI: J2.91(HDMITX_SDA/I2C5_SDA_M1/GPIO4_D0) Q4.2(SOURCE) R105.2
I2C5_SDA_M0: J2.76(LCDC_D19/VOP_BT1120_D10/GMAC1_R) Q16.3(DRAIN) R326.1 R329.2
I2C_SCL_RTC: R328.1 U21.6(SCL)
I2C_SDA_RTC: R329.1 U21.5(SDA)
LAN0_A+: D57.A(I/O2) D84.4 J22.2(MDI_0+) R223.2
LAN0_A-: D57.C(I/O1) D84.3 J22.3(MDI_0-) R222.2
LAN0_B+: D56.A(I/O2) D84.6 J22.4(MDI_1+) R221.2
LAN0_B-: D56.C(I/O1) D84.1 J22.7(MDI_1-) R220.2
LAN0_C+: D55.A(I/O2) D83.4 J22.5(MDI_2+) R425.2
LAN0_C-: D55.C(I/O1) D83.3 J22.6(MDI_2-) R424.2
LAN0_D+: D54.A(I/O2) D83.6 J22.8(MDI_3+) R215.2
LAN0_D-: D54.C(I/O1) D83.1 J22.9(MDI_3-) R214.2
LAN1_A+: D61.A(I/O2) D82.4 J23.2(MDI_0+) R266.2
LAN1_A-: D61.C(I/O1) D82.3 J23.3(MDI_0-) R265.2
LAN1_B+: D60.A(I/O2) D82.6 J23.4(MDI_1+) R264.2
LAN1_B-: D60.C(I/O1) D82.1 J23.7(MDI_1-) R263.2
LAN1_C+: D59.A(I/O2) D81.4 J23.5(MDI_2+) R262.2
LAN1_C-: D59.C(I/O1) D81.3 J23.6(MDI_2-) R261.2
LAN1_D+: D58.A(I/O2) D81.6 J23.8(MDI_3+) R260.2
LAN1_D-: D58.C(I/O1) D81.1 J23.9(MDI_3-) R259.2
LVDS_EN_GPIO3_A2: J2.65(LCDC_D9/VOP_BT1120_D1/GMAC1_TXD) R137.2
LVDS_ON_: J18.4 Q7.2(SOURCE) R133.2 R135.2
LVDS_ON_GPIO3_A1: J2.67(LCDC_D8/VOP_BT1120_D0/SPI1_CS0_) Q7.3(DRAIN) R132.2 R135.1
LVDS_PWM13: J18.3 R138.2 U14.4(Y)
LVDS_TX0_CLKN: J16.15 R127.2
LVDS_TX0_CLKP: J16.16 R126.2
LVDS_TX0_D0N: J16.7 R122.8
LVDS_TX0_D0P: J16.8 R122.7
LVDS_TX0_D1N: J16.9 R122.6
LVDS_TX0_D1P: J16.10 R122.5
LVDS_TX0_D2N: J16.11 R123.8
LVDS_TX0_D2P: J16.12 R123.7
LVDS_TX0_D3N: J16.17 R123.6
LVDS_TX0_D3P: J16.18 R123.5
MIC1_INN: C66.2 D97.2(I/O1) J2.250(MIC1_INN)
MIC1_INP: C64.2 J2.248(MIC1_INP)
MIPI_CSI_CLK0N: D99.1 D99.10 J19.17 R148.2
MIPI_CSI_CLK0P: D99.2 D99.9 J19.18 R147.2
MIPI_CSI_CLK1N: D105.1(I/O2) J20.17 R158.2
MIPI_CSI_CLK1P: D106.1(I/O2) J20.18 R157.2
MIPI_CSI_D0N: D98.1 D98.10 J19.11 R139.8
MIPI_CSI_D0P: D98.2 D98.9 J19.12 R139.7
MIPI_CSI_D1N: D98.4 D98.7 J19.14 R139.6
MIPI_CSI_D1P: D98.5 D98.6 J19.15 R139.5
MIPI_CSI_D2N: D99.4 D99.7 J19.20 R140.8
MIPI_CSI_D2N_: D104.1 D104.10 J20.11 R141.5
MIPI_CSI_D2P: D99.5 D99.6 J19.21 R140.7
MIPI_CSI_D2P_: D104.2 D104.9 J20.12 R141.6
MIPI_CSI_D3N: D100.1(I/O2) J19.23 R140.6
MIPI_CSI_D3N_: D104.4 D104.7 J20.14 R141.7
MIPI_CSI_D3P: D101.1(I/O2) J19.24 R140.5
MIPI_CSI_D3P_: D104.5 D104.6 J20.15 R141.8
MIPI_CSI_RX_CLK0N: J2.103(MIPI_CSI_RX_CLK0N) R148.1
MIPI_CSI_RX_CLK0P: J2.101(MIPI_CSI_RX_CLK0P) R147.1
MIPI_CSI_RX_CLK1N: J2.99(MIPI_CSI_RX_CLK1N) R158.1
MIPI_CSI_RX_CLK1P: J2.97(MIPI_CSI_RX_CLK1P) R157.1
MIPI_CSI_RX_D0N: J2.119(MIPI_CSI_RX_D0N) R139.1
MIPI_CSI_RX_D0P: J2.117(MIPI_CSI_RX_D0P) R139.2
MIPI_CSI_RX_D1N: J2.115(MIPI_CSI_RX_D1N) R139.3
MIPI_CSI_RX_D1P: J2.113(MIPI_CSI_RX_D1P) R139.4
MIPI_CSI_RX_D2N: J2.111(MIPI_CSI_RX_D2N) R140.1 R141.4
MIPI_CSI_RX_D2P: J2.109(MIPI_CSI_RX_D2P) R140.2 R141.3
MIPI_CSI_RX_D3N: J2.107(MIPI_CSI_RX_D3N) R140.3 R141.2
MIPI_CSI_RX_D3P: J2.105(MIPI_CSI_RX_D3P) R140.4 R141.1
MIPI_DSI_TX0_CLKN: D51.2 D51.9 J2.133(MIPI_DSI_TX0_CLKN/LVDS_TX0_CLKN) J15.27 R127.1
MIPI_DSI_TX0_CLKP: D51.1 D51.10 J2.131(MIPI_DSI_TX0_CLKP/LVDS_TX0_CLKP) J15.26 R126.1
MIPI_DSI_TX0_D0N: D53.1(I/O2) J2.141(MIPI_DSI_TX0_D0N/LVDS_TX0_D0N) J15.33 R122.1
MIPI_DSI_TX0_D0P: D52.1(I/O2) J2.139(MIPI_DSI_TX0_D0P/LVDS_TX0_D0P) J15.32 R122.2
MIPI_DSI_TX0_D1N: D51.5 D51.6 J2.137(MIPI_DSI_TX0_D1N/LVDS_TX0_D1N) J15.30 R122.3
MIPI_DSI_TX0_D1P: D51.4 D51.7 J2.135(MIPI_DSI_TX0_D1P/LVDS_TX0_D1P) J15.29 R122.4
MIPI_DSI_TX0_D2N: D49.5 D49.6 J2.129(MIPI_DSI_TX0_D2N/LVDS_TX0_D2N) J15.24 R123.1
MIPI_DSI_TX0_D2P: D49.4 D49.7 J2.127(MIPI_DSI_TX0_D2P/LVDS_TX0_D2P) J15.23 R123.2
MIPI_DSI_TX0_D3N: D49.2 D49.9 J2.125(MIPI_DSI_TX0_D3N/LVDS_TX0_D3N) J15.21 R123.3
MIPI_DSI_TX0_D3P: D49.1 D49.10 J2.123(MIPI_DSI_TX0_D3P/LVDS_TX0_D3P) J15.20 R123.4
MIPI_DSI_TX0_RST: C90.2 J15.36 R121.2 R417.2
MIPI_DSI_TX0_RST_GPIO4_C3: J2.136(PWM14_M1/SPI3_CLK_M1/CAN1_RX_M1) R417.1
MIPI_DSI_TX1_CLKN: D37.2 D37.9 J2.96(MIPI_DSI_TX1_CLKN) J13.27
MIPI_DSI_TX1_CLKP: D37.1 D37.10 J2.94(MIPI_DSI_TX1_CLKP) J13.26
MIPI_DSI_TX1_D0N: D38.1(I/O2) J2.104(MIPI_DSI_TX1_D0N) J13.33
MIPI_DSI_TX1_D0P: D36.1(I/O2) J2.102(MIPI_DSI_TX1_D0P) J13.32
MIPI_DSI_TX1_D1N: D37.5 D37.6 J2.100(MIPI_DSI_TX1_D1N) J13.30
MIPI_DSI_TX1_D1P: D37.4 D37.7 J2.98(MIPI_DSI_TX1_D1P) J13.29
MIPI_DSI_TX1_D2N: D35.5 D35.6 J2.92(MIPI_DSI_TX1_D2N) J13.24
MIPI_DSI_TX1_D2P: D35.4 D35.7 J2.90(MIPI_DSI_TX1_D2P) J13.23
MIPI_DSI_TX1_D3N: D35.2 D35.9 J2.88(MIPI_DSI_TX1_D3N) J13.21
MIPI_DSI_TX1_D3P: D35.1 D35.10 J2.86(MIPI_DSI_TX1_D3P) J13.20
MIPI_DSI_TX1_RST: C80.2 J13.36 R98.2 R418.2
MIPI_TX0_BL_PWM13: R110.2 R118.2 R138.1 U13.4(EN) U14.2(A)
MIPI_TX1_BL_PWM12: R91.2 R100.2 U12.4(EN)
MIPI_TX1_BL_PWM12_M0: J2.70(LCDC_D22/PWM12_M0/GMAC1_TXEN_M0) R91.1
MIPI_TX1_RST_GPIO2_D4: J2.79(LCDC_D4/VOP_BT656_D4_M0/SPI2_CS)
MIPI_TX1_RST_GPIO2_D6: J2.75(LCDC_D6/VOP_BT656_D6_M0/SPI2_MO) R418.1
NTC_SARADC_VIN3: J2.5(SARADC_VIN3) R312.2
PCIE20_CLKREQN_3V3_L: J27.52(PCIE_CLKREQ#(IO)(3.3V)) R348.2
PCIE20_CLKREQN_M2_3V3_L: J2.2(I2S1_SDO1_M0/I2S1_SDI3_M0/PDM_S) R348.1
PCIE20_PERSTN_3V3_L: J27.50(PCIE_PERST#(I)(3.3V)) R347.2
PCIE20_PERSTN_M2_3V3_L: J2.6(I2S1_SDO3_M0/I2S1_SDI1_M0/PDM_S) R347.1
PCIE20_PRSNT_3V3_L: J27.69(PEDET(NC-PCIE)(GND-SATA)) R382.1
PCIE20_PRSNT_3V3_L_GPIO3_A6: J2.57(LCDC_D13/VOP_BT1120_CLK/GMAC1_T) R382.2
PCIE20_REFCLKN: J2.184(PCIE20_REFCLKN) R360.1
PCIE20_REFCLKN_: J27.53(REFCLKN) R360.2
PCIE20_REFCLKP: J2.182(PCIE20_REFCLKP) R361.1
PCIE20_REFCLKP_: J27.55(REFCLKP) R361.2
PCIE20_RXN: J2.188(PCIE20_RXN/SATA2_RXN/QSGMII_RXN) R355.1
PCIE20_RXN_: J27.41(PETN0/SATA-B+) R355.2
PCIE20_RXP: J2.186(PCIE20_RXP/SATA2_RXP/QSGMII_RXP) R356.1
PCIE20_RXP_: J27.43(PETP0/SATA-B-) R356.2
PCIE20_TX_N: C212.2 R357.1
PCIE20_TX_P: C213.2 R358.1
PCIE20_TXN: C212.1 J2.192(PCIE20_TXN/SATA2_TXN/QSGMII_TXN)
PCIE20_TXN_: J27.47(PERN0/SATA-A-) R357.2
PCIE20_TXP: C213.1 J2.190(PCIE20_TXP/SATA2_TXP/QSGMII_TXP)
PCIE20_TXP_: J27.49(PERP0/SATA-A+) R358.2
PCIE20_WAKEN_3V3_L: J27.54(PCIE_PEWAKE#(IO)(3.3V)) R349.2
PCIE20_WAKEN_M2_3V3_L: J2.4(I2S1_SDO2_M0/I2S1_SDI2_M0/PDM_S) R349.1
PHY0_CLKOUT125: R216.2 U19.35(CLKOUT)
PHY0_G_LED-: J22.12(G_LED-) R213.1
PHY0_LED0/CFG_EXT: R225.2 R226.1 U19.32(LED0/CFG_EXT)
PHY0_LED1/CFG_LDO0: C133.2 J22.11(G_LED+) R233.2 U19.33(LED1/CFG_LDO0)
PHY0_LED2/CFG_LDO1: C132.2 J22.13(Y_LED-) R229.2 R230.1 U19.34(LED2/CFG_LDO1)
PHY0_MDI0+: R223.1 U19.1(MDI[0]+)
PHY0_MDI0-: R222.1 U19.2(MDI[0]-)
PHY0_MDI1+: R221.1 U19.4(MDI[1]+)
PHY0_MDI1-: R220.1 U19.5(MDI[1]-)
PHY0_MDI2+: R425.1 U19.6(MDI[2]+)
PHY0_MDI2-: R424.1 U19.7(MDI[2]-)
PHY0_MDI3+: R215.1 U19.9(MDI[3]+)
PHY0_MDI3-: R214.1 U19.10(MDI[3]-)
PHY0_REG_OUT: L22.1 U19.30(REG_OUT)
PHY0_RSTN: C143.2 R248.2 U19.12(PHYRSTB)
PHY0_RXCLK/PHYAD1: R237.2 R238.1 R256.1 U19.27(RXC/PHYAD1)
PHY0_RXD0/RXDLY: R239.2 R240.1 R252.1 U19.25(RXD0/RXDLY)
PHY0_RXD1/TXDLY: R242.2 R243.1 R253.1 U19.24(RXD1/TXDLY)
PHY0_RXD2/PLLOFF: R245.2 R246.1 R254.1 U19.23(RXD2/PLLOFF)
PHY0_RXD3/PHYAD0: R236.1 R255.1 U19.22(RXD3/PHYAD0)
PHY0_RXDV/PHYAD2: R235.2 R257.1 U19.26(RXCTL/PHYAD2)
PHY0_XTALIN: C130.2 U19.36(XTAL_IN) XT3.3
PHY0_XTALOUT: C129.2 U19.37(XTAL_OUT/EXT_CLK) XT3.1
PHY0_Y_LED+: J22.14(Y_LED+) R211.1
PHY1_CLKOUT125: R270.2 U20.35(CLKOUT)
PHY1_G_LED-: J23.12(G_LED-) R268.1
PHY1_LED0/CFG_EXT: R273.2 R274.1 U20.32(LED0/CFG_EXT)
PHY1_LED1/CFG_LDO0: C157.2 J23.11(G_LED+) R281.2 U20.33(LED1/CFG_LDO0)
PHY1_LED2/CFG_LDO1: C156.2 J23.13(Y_LED-) R277.2 R278.1 U20.34(LED2/CFG_LDO1)
PHY1_MDI0+: R266.1 U20.1(MDI[0]+)
PHY1_MDI0-: R265.1 U20.2(MDI[0]-)
PHY1_MDI1+: R264.1 U20.4(MDI[1]+)
PHY1_MDI1-: R263.1 U20.5(MDI[1]-)
PHY1_MDI2+: R262.1 U20.6(MDI[2]+)
PHY1_MDI2-: R261.1 U20.7(MDI[2]-)
PHY1_MDI3+: R260.1 U20.9(MDI[3]+)
PHY1_MDI3-: R259.1 U20.10(MDI[3]-)
PHY1_REG_OUT: L23.1 U20.30(REG_OUT)
PHY1_RSTN: C167.2 R296.2 U20.12(PHYRSTB)
PHY1_RXCLK/PHYAD1: R284.2 R285.1 R304.1 U20.27(RXC/PHYAD1)
PHY1_RXD0/RXDLY: R287.2 R288.1 R300.1 U20.25(RXD0/RXDLY)
PHY1_RXD1/TXDLY: R290.2 R291.1 R301.1 U20.24(RXD1/TXDLY)
PHY1_RXD2/PLLOFF: R293.2 R294.1 R302.1 U20.23(RXD2/PLLOFF)
PHY1_RXD3/PHYAD0: R283.1 R303.1 U20.22(RXD3/PHYAD0)
PHY1_RXDV/PHYAD2: R286.2 R305.1 U20.26(RXCTL/PHYAD2)
PHY1_XTALIN: C153.2 U20.36(XTAL_IN) XT4.3
PHY1_XTALOUT: C154.2 U20.37(XTAL_OUT/EXT_CLK) XT4.1
PHY1_Y_LED+: J23.14(Y_LED+) R267.1
PWM3_IR: J2.124(PWM3_IR/EDP_HPDIN_M1/PCIE30X1_W) R311.3
PWM3_IR_: J24.23 R311.6
PWM13_M1: J2.144(PWM13_M1/SPI3_CS0_M1/SATA0_ACT_) R110.1
PWRON: J24.25 R314.2
RESET: J24.26 R311.5
RK809-CLK32K: J2.247(RK809-CLK32K) R205.1
RK809_PWRON: C259.2 J2.251(RK809_PWRON) R314.1 R412.1
RK809_VDC: J2.252(RK809_VDC) R7.1 R9.2
RSET0: R241.2 U19.39(RSET)
RSET1: R289.2 U20.39(RSET)
RTCIC_32KOUT: R206.1 U21.7(CLKOUT)
SARADC_VIN0_: J24.27 R312.8
SARADC_VIN0_KEY/RECOVERY: C182.2 J2.1(SARADC_VIN0_KEY/RECOVERY) R312.1 R330.1
SARADC_VIN2_: J24.29 R312.6
SARADC_VIN2_HP_HOOK: J2.3(SARADC_VIN2_HP_HOOK) R312.3
SARADC_VIN3_: J24.28 R312.7
SARADC_VIN4: J2.7(SARADC_VIN4) R312.4
SARADC_VIN4_: J24.30 R312.5
SCL_CAM0: D102.2 D102.9 J19.7 R152.2 R159.1
SCL_CAM1: D103.2 D103.9 J20.7 Q17.2(SOURCE) R159.2 R162.1
SDA_CAM0: D102.4 D102.7 J19.8 R153.2 R160.1
SDA_CAM1: D103.4 D103.7 J20.8 Q16.2(SOURCE) R160.2 R161.1
SDMMC0_CLK: J2.206(SDMMC0_CLK/TEST_CLKOUT/UART5_TX) R21.1
SDMMC0_CLK_: C30.2 D4.1 D4.10 J3.5(CLK) R21.2
SDMMC0_CMD: J2.204(SDMMC0_CMD/PWM10_M1/UART5_RX_M0) R20.1
SDMMC0_CMD_: D3.5 D3.6 J3.3(CMD) R20.2
SDMMC0_D0: J2.196(SDMMC0_D0/UART2_TX_M1/UART6_TX_) R22.1
SDMMC0_D0_: D4.2 D4.9 J3.7(DATA0) R22.2
SDMMC0_D1: J2.198(SDMMC0_D1/UART2_RX_M1/UART6_RX_) R23.1
SDMMC0_D1_: D4.4 D4.7 J3.8(DATA1) R23.2
SDMMC0_D2: J2.200(SDMMC0_D2/ARMJTAG_TCK/UART5_CTS) R18.1
SDMMC0_D2_: D3.2 D3.9 J3.1(DATA2) R18.2
SDMMC0_D3: J2.202(SDMMC0_D3/ARMJTAG_TMS/UART5_RTS) R19.1
SDMMC0_D3_: D3.4 D3.7 J3.2(CD/DATA3) R19.2
SDMMC0_DET_: D4.5 D4.6 J3.9(CD) R24.2
SDMMC0_DET_L: J2.208(SDMMC0_DET/SATA_CP_DET/PCIE30X1) R24.1
SDMMC2_CLK_M0: J2.27(CIF_D5/EBC_SDDO5/SDMMC2_CLK_M0/) R187.1
SDMMC2_CMD_M0: J2.25(CIF_D4/EBC_SDDO4/SDMMC2_CMD_M0/) R185.2 R186.1
SDMMC2_D0_M0: J2.17(CIF_D0/EBC_SDDO0/SDMMC2_D0_M0/I) R180.2 R181.1
SDMMC2_D1_M0: J2.19(CIF_D1/EBC_SDDO1/SDMMC2_D1_M0/I) R182.1
SDMMC2_D2_M0: J2.21(CIF_D2/EBC_SDDO2/SDMMC2_D2_M0/I) R183.1
SDMMC2_D3_M0: J2.23(CIF_D3/EBC_SDDO3/SDMMC2_D3_M0/I) R184.1
SPI0_CLK: J24.3 R315.6
SPI0_CLK_M1: J2.81(LCDC_D3/VOP_BT656_D3_M0/SPI0_CL) R315.3
SPI0_CS0: J24.4 R315.5
SPI0_CS0_M1: J2.83(LCDC_D2/VOP_BT656_D2_M0/SPI0_CS) R315.4
SPI0_MISO: J24.2 R315.7
SPI0_MISO_M1: J2.87(LCDC_D0/VOP_BT656_D0_M0/SPI0_MI) R315.2
SPI0_MOSI: J24.1 R315.8
SPI0_MOSI_M1: J2.85(LCDC_D1/VOP_BT656_D1_M0/SPI0_MO) R315.1
SPK_CTL_H_GPIO3_B0: J2.53(LCDC_D15/VOP_BT1120_D6/ETH1_REF) R89.1
SPK_MUTE_H_GPIO3_A7: J2.55(LCDC_D14/VOP_BT1120_D5/GMAC1_RX) R90.1
SYS_LED_GPIO4_C5: J2.142(PWM12_M1/SPI3_MISO_M1/SATA1_ACT) R8.1
SYS_RESETN: J2.235(SYS_RESETN) R311.4
TP0_INT: D48.4 D48.7 J15.5 J31.3 R114.2
TP0_INT_L_GPIO3_A3: J2.63(LCDC_D10/VOP_BT1120_D2/GMAC1_TX) R114.1
TP0_RST: D48.5 D48.6 J15.4 J31.2 R113.2
TP0_RST_L_GPIO3_A4: J2.61(LCDC_D11/VOP_BT1120_D3/GMAC1_RX) R113.1
TP0_SCL: D48.2 D48.9 J15.6 J31.4 R115.2
TP0_SDA: D48.1 D48.10 J15.7 J31.5 R116.2
TP1_INT: D34.2 D34.9 J13.5 R95.2
TP1_INT_L_GPIO3_C0: J2.68(LCDC_D23/PWM13_M0/GMAC1_MCLKINO) R95.1
TP1_RST: D34.1 D34.10 J13.4 R94.2
TP1_RST_L_GPIO3_C1: J2.66(LCDC_HSYNC/VOP_BT1120_D13/SPI1_) R94.1
TP1_SCL: D34.4 D34.7 J13.6 R96.2
TP1_SDA: D34.5 D34.6 J13.7 R97.2
TYPEC_CC1: D8.2(I/O1) D11.C J5.A5(CC1) R38.1
TYPEC_CC2: D9.2(I/O1) D13.C J5.B5(CC2) R40.1
UART0_CTSN: J2.134(HDMITX_CEC_M1/PWM0_M1/UART0_CTS) R310.2
UART0_CTSN_: J24.16 R310.7
UART0_RTSN: J2.128(PWM5/SPI0_CS1_M0/UART0_RTSN/GPI) R310.1
UART0_RTSN_: J24.15 R310.8
UART0_RX: J2.120(PWM1_M0/GPUAVS/UART0_RX/GPIO0_C) R309.3
UART0_RX_: J24.14 R309.6
UART0_TX: J2.122(PWM2_M0/NPUAVS/UART0_TX/MCU_JTA) R309.4
UART0_TX_: J24.13 R309.5
UART2_RX_M0: J2.116(UART2_RX_M0/GPIO_D0_U) R25.1
UART2_TX_M0: J2.118(UART2_TX_M0/GPIO_D1_U) R26.1
UART4_RX: J24.12 R309.7
UART4_RX_M1: J2.82(LCDC_D16/VOP_BT1120_D7/GMAC1_RX) R309.2
UART4_TX: J24.11 R309.8
UART4_TX_M1: J2.80(LCDC_D17/VOP_BT1120_D8/GMAC1_RX) R309.1
UART5_RX: J24.10 R316.6
UART5_RX_M1: J2.62(LCDC_DEN/VOP_BT1120_D15/SPI1_CL) R316.3
UART5_TX: J24.9 R316.5
UART5_TX_M1: J2.64(LCDC_VSYNC/VOP_BT1120_D14/SPI1_) R316.4
UART7_RX: J24.7 R316.8
UART7_RX_M1: J2.58(PWM15_IR_M0/SPDIF_TX_M1/GMAC1_M) R316.1
UART7_TX: J24.8 R316.7
UART7_TX_M1: J2.60(PWM14_M0/VOP_PWM_M1/GMAC1_MDC_M) R316.2
UART8_CTSN_M0: J2.233(SDMMC1_DET/I2C4_SCL_M1/UART8_CT) R201.1 U18.41(UART_RTS_N)
UART8_RTSN_M0: J2.231(SDMMC1_PWREN/I2C4_SDA_M1/UART8_) U18.44(UART_CTS_N)
UART8_RX_M0: J2.238(CLK32K_OUT1/UART8_RX_M0/SPI1_CS) U18.42(UART_TXD)
UART8_TX_M0: J2.236(I2S2_SDI_M0/GMAC0_RXER/UART8_TX) U18.43(UART_RXD)
USB1_PWREN_H_GPIO3_A5: J2.59(LCDC_D12/VOP_BT1120_D4/GMAC1_RX) R57.1
USB2_HOST2_DM: J2.28(USB2_HOST2_DM) L6.2 R42.1
USB2_HOST2_DM_: D14.5 D14.6 J6.2(1D-) L6.3 R42.2
USB2_HOST2_DP: J2.26(USB2_HOST2_DP) L6.1 R43.1
USB2_HOST2_DP_: D14.4 D14.7 J6.3(1D+) L6.4 R43.2
USB2_HOST2_PWREN_H_GPIO0_A6: J2.110(GPU_PWREN/SATA_CP_POD/PCIE30X2_) U5.4(EN)
USB2_HOST3_DM: J2.24(USB2_HOST3_DM) R71.2
USB2_HOST3_DP: J2.22(USB2_HOST3_DP) R69.2
USB2_PWREN_H_GPIO4_C3: J2.138(PWM15_IR_M1/SPI3_MOSI_M1/CAN1_T) R70.1
USB3_HOST1_DM: J2.169(USB3_HOST1_DM) L7.2 R46.1
USB3_HOST1_DM_: D14.2 D14.9 J6.11(2D-) L7.3 R46.2
USB3_HOST1_DP: J2.167(USB3_HOST1_DP) L7.1 R47.1
USB3_HOST1_DP_: D14.1 D14.10 J6.12(2D+) L7.4 R47.2
USB3_HOST1_PWREN_H_GPIO3_A0: J2.71(LCDC_CLK/VOP_BT656_CLK_M0/SPI2_) U6.4(EN)
USB3_HOST1_SSRXN: J2.175(USB3_HOST1_SSRXN/SATA1_RXN/QSGM) R375.1 R423.1
USB3_HOST1_SSRXN_: D17.1 D17.10 J6.14(RX2-) R375.2
USB3_HOST1_SSRXP: J2.177(USB3_HOST1_SSRXP/SATA1_RXP/QSGM) R376.1 R422.1
USB3_HOST1_SSRXP_: D17.2 D17.9 J6.15(RX+) R376.2
USB3_HOST1_SSTXN: C187.1 C290.1 J2.171(USB3_HOST1_SSTXN/SATA1_TXN/QSGM)
USB3_HOST1_SSTXN_: C290.2 D17.4 D17.7 J6.17(TX2-)
USB3_HOST1_SSTXP: C189.1 C291.1 J2.173(USB3_HOST1_SSTXP/SATA1_TXP/QSGM)
USB3_HOST1_SSTXP_: C291.2 D17.5 D17.6 J6.18(TX2+)
USB3_OTG0_DM: J2.189(USB3_OTG0_DM) L5.2 R29.1
USB3_OTG0_DM_: D12.2(I/O1) J5.A7(DM1) J5.B7(DM2) L5.3 R29.2
USB3_OTG0_DP: J2.187(USB3_OTG0_DP) L5.1 R34.1
USB3_OTG0_DP_: D10.2(I/O1) J5.A6(DP1) J5.B6(DP2) L5.4 R34.2
USB3_OTG0_ID: J2.193(USB3_OTG0_ID) Q1.3(DRAIN) R31.2
USB3_OTG0_SSRXN: J2.183(USB3_OTG0_SSRXN/SATA0_RXN) R48.1
USB3_OTG0_SSRXN_: D107.1 D107.10 J6.5(RX1-) R48.2
USB3_OTG0_SSRXP: J2.185(USB3_OTG0_SSRXP/SATA0_RXP) R49.1
USB3_OTG0_SSRXP_: D107.2 D107.9 J6.6(RX1+) R49.2
USB3_OTG0_SSTXN: C39.1 J2.179(USB3_OTG0_SSTXN/SATA0_TXN)
USB3_OTG0_SSTXN_: C39.2 D107.4 D107.7 J6.8(TX1-)
USB3_OTG0_SSTXP: C41.1 J2.181(USB3_OTG0_SSTXP/SATA0_TXP)
USB3_OTG0_SSTXP_: C41.2 D107.5 D107.6 J6.9(TX1+)
USB3_OTG0_VBUSDET: J2.191(USB3_OTG0_VBUSDET) R27.2 R28.2
USB3_PWREN_H_GPIO4_C4: J2.140(EDP_HPDIN_M0/SPDIF_TX_M2/SATA2_) R77.1
USB_OTG_PWREN_H_GPIO0_A5: J2.212(SDMMC0_PWREN/SATA_MP_SWITCH/PCI) R32.1
USIM_CLK: C185.1 D75.1(I/O2) R335.2 SIM1.C3(CLK)
USIM_CLK_: J26.12(USIM_CLK) R335.1
USIM_DATA: C188.1 D73.1(I/O2) R331.1 R334.2 SIM1.C7(DATA)
USIM_DATA_: J26.10(USIM_IO) R334.1
USIM_RST: C184.1 D72.1(I/O2) R332.2 R336.2 SIM1.C2(RESET)
USIM_RST_: J26.14(USIM_RESET) R336.1
USIM_VDD: C183.1 C186.1 D74.1(I/O2) R331.2 R332.1 R333.2 SIM1.C1(VDD)
VOLN: C73.1 D30.2(I/O1) J12.1 L11.2
VOLP: C74.1 D31.2(I/O1) J12.2 L12.2
VORN: C76.1 D32.2(I/O1) J12.3 L13.2
VORP: C77.1 D33.2(I/O1) J12.4 L14.2
WIFI1T1R_CLK: C112.2 R187.2 U18.17(SDIO_DATA_CLK)
WIFI1T1R_CMD: R186.2 U18.16(SDIO_DATA_CMD)
WIFI1T1R_D0: R181.2 U18.18(SDIO_DATA_0)
WIFI1T1R_D1: R182.2 U18.19(SDIO_DATA_1)
WIFI1T1R_D2: R183.2 U18.14(SDIO_DATA_2)
WIFI1T1R_D3: R184.2 U18.15(SDIO_DATA_3)
WIFI1T1R_XTAL_IN: C114.1 U18.10(XTAL_IN) XT2.3
WIFI1T1R_XTAL_OUT: R191.2 U18.11(XTAL_OUT)
WIFI_PWREN_L_GPIO0_B7: J2.114(PWM0-M0/CPUAVS/GPIO0_B7_D) R207.2
WIFI_REG_ON_H_GPIO3_D5: J2.33(CIF_D7/EBC_SDDO7/SDMMC2_PWREN_M) R196.1 R210.1
WIFI_WAKE_HOST_H_GPIO3_D4: J2.29(CIF_D6/EBC_SDDO6/SDMMC2_DET_M0/) U18.13(WL_HOST_WAKE)
WIFIBT_32KIN_1T1R: C126.2 R204.2 R205.2 R206.2 U18.24(LPO)
N17053074: C113.2 C115.2 U18.2(WL_BT_ANT)
N17053234: C113.1 C116.2 J21.2(SIG)
N68563646: C179.2 U21.1(OSCI) XT5.2
N68563661: C180.2 U21.2(OSCO) XT5.1
N69300963: C2.2 D1.A(I/O2) F2.2 L1.1 R1.1
N69811939: C12.2 R3.1 R5.2 U1.5(EN)
N69812073: C1.1 L2.1 U1.2(LX)
N69812091: C1.2 U1.4(BS)
N69812134: C8.1 R4.1 R6.2 U1.6(FB)
N69812831: C13.1 L3.1 U2.2(LX)
N69812843: C17.1 R11.1 R12.2 U2.6(FB)
N69812998: C13.2 U2.4(BS)
N69813915: R13.2 U2.5(EN)
N69814391: L4.1 U3.3(SW)
N69814410: C24.1 R15.1 R16.2 U3.5(FB)
N69814930: R14.2 U3.1(EN)
N69815076: LED1.3 R10.2
N69815079: LED1.1 R8.2
N69817092: D5.2(I/O1) J4.1 R25.2
N69817095: D6.2(I/O1) J4.2 R26.2
N69818339: R58.1 U8.1(OVCB_2)
N69818343: R55.1 U8.7(OVCB_4)
N69818347: R54.1 U8.5(OVCB_3)
N69818991: C44.2 R61.1 U8.39(VD33_OUT)
N69818999: R59.2 U8.48(OVCB_1)
N69819001: R65.2 U8.36(BUS_B)
N69819016: R73.1 U8.28(REXT)
N69819018: C45.2 U8.38(VD5_IN)
N69820056: R45.2 U5.3(OCB)
N69820298: R51.2 U6.3(OCB)
N69820533: R57.2 U7.4(EN)
N69820554: R60.2 U7.3(OCB)
N69820805: R70.2 U9.4(EN)
N69820826: R72.2 U9.3(OCB)
N69821095: R77.2 U10.4(EN)
N69821116: R79.2 U10.3(OCB)
N69821410: R32.2 R36.2 U4.4(EN)
N69821431: R33.2 U4.3(OCB)
N69829177: Q1.1(GATE) Q2.3(DRAIN) R30.1 R31.1 R35.2
N69829182: D11.A D13.A R37.1 R38.2 R39.1 R40.2
N69829189: C35.2 Q2.1(GATE) R35.1 R39.2 R41.2
N69844387: C63.1 R80.2 R83.2
N69844453: C64.1 C65.2 D29.2(I/O1) J11.1 R83.1
N69844782: D27.2(I/O1) J10.2(R) R82.2
N69844789: D28.2(I/O1) J10.3(L) R84.2
N69846177: C72.1 R87.1
N69846180: R87.2 U11.7(INL)
N69846237: C75.1 R88.1
N69846239: R88.2 U11.10(INR)
N69846282: C71.2 U11.8(BYPASS)
N69846442: Q14.3(DRAIN) U11.5(M\U\T\E\)
N69846447: Q15.3(DRAIN) U11.12(S\D\)
N69846810: L11.1 U11.3(VOLN)
N69846813: L12.1 U11.1(VOLP)
N69846816: L13.1 U11.14(VORN)
N69846819: L14.1 U11.16(VORP)
N69847759: D42.C R104.2 R106.1
N69853313: C246.1 Q12.1(GATE) R391.1 R392.1
N69853352: Q13.3(DRAIN) R392.2
N69854514: Q13.1(GATE) R393.1
N69857283: R172.1 R173.2 U15.4(ADJ)
N69857307: C108.2 R175.1 R176.2 U16.4(ADJ)
N69857397: R177.1 R179.2 U17.4(ADJ)
N69863572: C117.2 R191.1 XT2.1
N69863896: R209.2 R210.2 U18.34(BT_RST_N)
N69864199: R208.2 U18.29(VDD_TCXO)
N69864441: R196.2 U18.12(WL_REG_ON)
N69864462: C127.2 C128.2 L21.2 U18.23(VIN_LDO)
N69864477: L21.1 U18.21(VIN_LDO_OUT)
N69866041: C124.1 Q10.1(GATE) R203.1 R207.1
N69873113: C142.2 J22.1(CT1/2/3/4)
N69883193: C166.2 J23.1(CT1/2/3/4)
N69887528: L24.1 U22.3(SW)
N69887530: C207.1 R343.1 R345.2 U22.5(FB)
N69887600: R344.2 U22.1(EN)
N69896427: J26.8(VREG_USIM) R333.1
N69897118: J26.22(PERST_N) R337.1
N69899428: J26.42(LED_WWAN) LED2.2(CATHODE)
N69899460: LED2.1(ANODE) R342.1
N69910248: D71.1(I/O2) R330.2 SW1.3
N69911722: R99.2 U12.3(FB)
N69911786: C78.2 J13.17 R413.2 R415.2
N69912226: D39.A L15.2 U12.1(LX)
N69922645: R117.2 U13.3(FB)
N69922778: D50.A L20.2 U13.1(LX)
N69927169: C92.1 Q6.1(GATE) R134.1 R136.1
N69927197: Q8.3(DRAIN) R136.2
N69927388: Q8.1(GATE) R137.1
N70033042: Q15.1(GATE) R89.2
N70033056: Q14.1(GATE) R90.2
N70059784: C258.2 J15.17 R408.2 R409.2
N70064377: D96.1(I/O2) R412.2 SW2.3

Pads without a net: D3 1 10; D81 5; D82 5; D83 5; D84 5; J1 5 6; J2 160 162 164 166 168 170 172 174 176 178 239 241 243; J5 A8 B8; J13 3 8 12 13 14 15 35 40; J15 3 8 12 13 14 15 35 40; J16 4 19 20; J20 20 21 23 24; J26 1 3 5 6 7 11 13 16 17 19 20 28 30 32 44 45 46 47 48 49 51; J27 5 6 7 8 10 11 13 17 19 20 22 23 24 25 26 28 29 30 31 32 34 35 36 37 38 40 42 44 46 48 56 58 67; J28 3 5 6 20; MARK1 1; MARK2 1; MARK3 1; MARK4 1; MARK* 1; MARK*#2 1; SIM1 C6 CD1 CD2; U8 2 4 8 43 44 45 46 47; U18 4 5 8 25 26 27 28 30 32 35 37 38 39 40 45 46 47; U19 31; U20 31; U21 3

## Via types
v1: diameter 0.55, hole 0.3, TOP to BOTTOM, 1878 vias
v2: diameter 0.45, hole 0.2, TOP to BOTTOM, 44 vias

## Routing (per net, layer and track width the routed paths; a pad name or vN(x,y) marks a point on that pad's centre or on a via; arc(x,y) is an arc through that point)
GND: length 4370.9
  TOP w0.127: v1(73.03,63.58) 73.03,64.26 73.99,65.23 75.96,65.23 C158.1 ; v1(95.71,28.22) 96.09,28.6 102.94,28.6 103.71,27.83 103.71,27.67 103.42,27.38 103.42,26.97 103.47,26.92 103.47,26.06 103.84,25.7 103.84,25.48 v1(104.06,25.26) ; J3.12 111.8,82.91 112.73,81.99 112.73,74.42 113.51,73.63 113.87,73.63 114.86,72.64 114.86,68.5 114.33,67.97 114.33,66.5 114.1,66.27 v1(114.1,66.12) ; D105.2 38.38,11.81 39.12,11.07 39.12,9.97 v1(39.46,9.63) ; 60.2,49.81 v1(60.22,49.81) 60.22,49.68 59.99,49.45 58.62,49.45 v1(58.12,48.95) 57.81,48.95 56.69,50.06 56.41,50.06 54.46,48.11 54.46,46.98 55.13,46.31 55.13,44.11 54.84,43.81 54.84,43.76 v1(54.79,43.71) ; v1(94.64,47.04) 94.69,46.99 94.69,46.3 ; 48.74,26.9 48.74,26.77 48.58,26.61 ; 48.74,26.9 v1(48.89,26.75) 48.76,26.61 48.58,26.61 ; 48.74,26.9 48.74,45.92 46.18,48.49 46.18,50.5 45.8,50.88 v1(45.8,51.36) ; v1(109.88,25.6) 110.08,25.81 110.08,28.88 108.03,30.94 97.13,30.94 96.62,31.45 96.62,43.74 97.1,44.22 97.1,46.3 96.85,46.56 94.95,46.56 94.69,46.3 ; v1(72.06,63.7) 72.06,64.06 74.12,66.12 76.98,66.12 C159.1 ; U21.4 78.72,34.1 78.69,34.14 78.69,35.08 78.49,35.28 76.58,35.28 76.3,35 76.3,33.25 76.15,33.1 76.15,31.72 v1(76.02,31.6) 76,31.57 75.77,31.57 75.46,31.27 75.46,28.96 75.77,28.65 78.77,28.65 79.27,29.16 79.27,31.24 v1(78.69,31.83) 78.69,34.01 ; v1(42.34,22.53) 42.34,22.5 42.49,22.35 43.05,22.35 43.26,22.56 46.56,22.56 47.7,23.7 47.7,25.73 48.58,26.61 ; 94.69,46.3 94.56,46.18 94.56,45.42 94.36,45.22 94.36,44.93 94.31,44.88 94.31,44.37 94.97,43.71 94.97,30.95 95.36,30.56 95.36,30.34 96.31,29.39 105.68,29.39 106.38,28.69 106.38,25.63 v1(106.1,25.35) ; v1(67.03,65.2) 67.44,65.2 67.54,65.3 69.06,65.3 C12.1 ; D25.1 102.28,6.84 101.93,7.19 101.93,8.23 102.34,8.64 102.34,11.28 v1(102.06,11.56) ; v1(72.44,70.03) 72.44,70.43 72.67,70.66 73.92,70.66 74.26,70.32 74.26,69.08 71.83,66.65 71.62,66.65 ; C97.1 56.4,50.77 53.95,48.32 53.95,46.77 54.58,46.14 54.58,44.6 53.96,43.97 53.96,43.95 53.95,43.94 53.95,42.88 53.95,42.5 53.29,41.84 53.29,39.45 52.02,38.18 52.02,31.45 52.78,30.68 52.78,21.67 ; 52.78,21.67 52.02,20.9 52.02,20.46 51.83,20.27 51.7,20.4 49.48,20.4 v1(49.4,20.32) ; 52.78,21.67 52.78,20.02 52.53,19.76 v1(52.53,19.63) v1(52.53,19.02) 52.53,17.86 52.4,17.73 52.4,16.97 ; 77.01,67.79 76.86,67.64 C259.1 ; v1(128.6,51.23) 129.62,52.25 129.62,54.94 130.53,55.85 131.75,55.85 132.28,55.32 132.28,54.43 131.01,53.16 J24.5 128.73,49.99 v1(128.6,49.99) ; 52.53,17.09 52.4,16.97 ; 52.4,16.97 v1(52.4,16.94) ; v1(47.96,20.32) 49.05,21.41 51.13,21.41 52.27,22.56 52.27,23.06 v1(52.04,23.29) 52.27,23.52 52.27,24.03 v1(52.04,24.26) 52.27,24.49 52.27,30.43 51.51,31.19 51.51,38.43 52.78,39.7 52.78,42.05 53.44,42.71 53.44,43.09 53.44,43.09 53.44,44.15 53.45,44.16 53.45,44.18 54.08,44.81 54.08,45.93 53.44,46.56 53.44,48.54 56.56,51.66 v1(57.07,51.66) ; v2(51.51,54.56) 51.46,54.51 50.44,54.51 50.29,54.66 50.29,55.4 51,56.11 51.92,56.11 52.48,55.55 v1(52.48,55.32) 53.21,54.58 v1(54.99,54.58) 55.83,54.58 v1(56.26,55.02) 56.72,55.47 v1(56.72,55.5) ; v1(77.11,50.18) 77.29,50 77.29,45.92 77.67,45.54 77.67,44.15 81.48,40.34 81.48,35.51 81.61,35.38 81.61,28.02 81.36,27.76 v1(81.36,27.38) 81.36,27 80.44,26.09 79.78,26.09 79.5,26.37 79.5,26.82 79.88,27.2 v1(80.34,27.2) 80.59,27.46 80.59,27.76 81.1,28.27 81.1,35.13 80.98,35.26 80.98,40.08 77.17,43.89 77.17,45.29 76.78,45.67 76.78,48.59 76.5,48.87 76.05,48.87 75.9,48.72 75.26,48.72 72.85,51.13 v1(72.85,51.77) ; 100.79,49.23 101.68,49.23 102.31,48.59 102.69,48.59 103.45,47.83 v1(104.22,47.83) ; v1(38.68,16.97) 39.62,16.97 40.08,16.51 40.08,14.4 v1(40.47,14.01) 40.63,14.01 42.37,12.27 v1(42.37,9.73) ; v2(76.99,72.09) 76.86,71.96 76.86,71.22 76.96,71.12 v2(76.96,71.12) 76.96,71.12 77.01,71.07 ; v1(34.44,50.85) 35.2,50.85 37.49,48.56 40.44,48.56 40.87,48.13 v1(40.87,47.83) ; D106.2 36.72,10.9 38.04,10.9 38.31,10.63 38.31,10.12 37.96,9.76 J20.19 ; v1(107.19,25.68) 107.16,25.7 107.16,28.63 105.87,29.92 97.31,29.92 96.5,29.92 95.87,30.55 95.87,30.77 95.48,31.16 95.48,31.41 95.55,31.48 95.55,31.69 95.55,44.58 95.05,45.09 95.05,45.21 v1(94.93,45.33) ; v1(86.46,53.42) 86.46,51.66 83.96,49.17 83.96,42.81 84.79,41.99 84.79,37.8 85.29,37.29 85.29,36.25 85.7,35.84 v1(85.7,35.81) 85.29,35.41 84.81,35.41 84.48,35.74 84.48,36.09 84.79,36.4 84.79,37.03 84.28,37.54 84.28,41.73 83.46,42.55 83.46,49.42 85.27,51.23 v1(85.27,51.54) ; v1(116,59.97) 115.82,59.97 115.65,60.15 115.01,60.15 114.63,59.77 v1(114.63,59.66) ; C167.1 53.8,41.5 53.8,39.21 52.55,37.96 52.55,37.94 52.53,37.92 52.53,31.7 53.29,30.94 53.29,28.88 v1(53.52,28.65) 53.29,28.42 53.29,18.03 v1(53.42,17.91) ; 129.57,60.73 128.85,60.02 v1(128.6,60.02) ; v1(30.96,46.94) 30.61,47.29 30.61,47.62 31.27,48.29 v1(32.92,48.29) ; v1(40.89,46.81) 40.89,47.14 40.49,47.55 39.6,47.55 39.09,48.06 37.24,48.06 35.41,49.89 v1(34.44,49.89) ; v1(94.13,30.05) 94.11,30.07 94.11,43.43 93.24,44.29 v1(93.24,44.6) ; v1(67.44,75.62) 67.31,75.74 66.45,75.74 66.23,75.95 65.98,75.95 65.27,76.66 65.23,76.66 D44.2 ; C95.1 76.09,50.67 75.01,50.67 v1(73.89,51.79) ; 113.36,82.8 113.23,82.68 113.23,74.68 113.77,74.14 114.12,74.14 115.39,72.87 115.39,68.25 114.86,67.72 114.86,66.32 115.11,66.07 v1(115.11,65.79)
  TOP w0.152: 77.01,71.07 77.01,67.79
  TOP w0.203: 14.78,50.22 14.14,50.22 13.59,49.67 13.17,49.67 H2.1 ; 14.78,50.22 14.78,47.44 14.96,47.27 14.96,37.69 16.08,36.58 16.08,36.58 16.08,34.44 18.69,31.83 22.94,31.83 24.46,30.3 24.66,30.1 25.22,30.1 25.35,29.97 25.35,29.41 27.89,26.87 33.66,26.87 v1(34.8,25.73) ; 14.78,50.22 16.36,51.79 20.37,51.79 20.37,52.7 J2.254 ; v1(131.39,65.48) 130.89,64.97 130.89,60.64 128.75,58.5 128.74,58.5 128.57,58.33 v1(128.57,58.22) ; XT1.4 114.51,33.92 v1(114.51,34.54) ; v1(114.51,34.54) 113.36,34.54 113.16,34.75 v1(112.09,34.75) ; v1(114.51,34.54) 115.59,34.54 115.79,34.34 115.79,30.45 115.52,30.18 v1(113.49,30.18) ; XT4.4 69.7,41.65 69.7,39.47 69.47,39.24 67.9,39.24 XT4.2 ; C25.1 37.23,25.92 37.8,26.49 37.8,27.05 37.69,27.15 v1(37.8,27.25) 37.8,27.51 35.89,29.41 28.73,29.41 28.73,29.44 28.71,29.44 27.79,30.36 27.79,31.84 27.11,32.51 25.63,32.51 23.77,34.37 19.99,34.37 v1(19.86,34.49) 19.1,35.26 19.1,45.25 ; J2.258 19.92,54.58 20.13,54.79 20.73,54.79 v1(20.83,54.69) v1(20.83,55.24) ; v1(42.49,40.59) 42.62,40.46 v1(43.38,40.46) 45.97,40.46 46.18,40.67 v1(46.18,43.13) 46.18,44.27 45.65,44.8 42.76,44.8 42.37,44.4 42.37,44.21 C129.1 ; v1(116,59.97) 116,59.36 115.52,58.88 115.52,58.27 115.16,57.91 115.16,54.97 115.27,54.86 115.27,54.79 ; v1(73.74,60.27) 73.67,60.34 J2.51 ; C141.1 36.71,45.36 36.02,46.05 v1(35.76,46.05) ; v1(23.93,56.67) 23.9,56.64 23.9,56.36 23.95,56.31 23.95,56.19 23.85,56.09 23.85,55.79 23.85,55.79 23.85,55.6 v1(23.65,55.4) ; 78.69,34.14 78.69,34.01 ; v1(17.58,42.62) 17.51,42.69 17.51,43.3 17.4,43.4 17.4,43.75 J2.N2 17.35,47 17.35,49.25 17.55,49.45 22.28,49.45 24.42,51.6 J2.240 ; U8.10 108.76,34.52 108.92,34.37 v1(108.92,31.95) 110.25,30.61 C51.1 111.13,30.61 v1(111.2,30.68) 111.33,30.56 111.96,30.56 112.34,30.18 113.48,30.18 ; C49.1 110.5,33.55 110.19,33.86 110.19,36.58 109.98,36.78 v1(108.76,36.78) ; v1(28.88,59.11) 28.78,59 28.78,56.59 v1(29.03,56.34) ; C180.1 78.49,31.63 v1(78.69,31.83) ; J2.158 44.92,52.23 v1(45.8,51.36) ; v1(27.89,58.98) 28.03,58.84 28.03,56.58 v1(27.91,56.46) ; v1(100.15,51.1) 100.41,51.36 v1(100.41,51.77) ; v1(76.02,31.6) 76.05,31.6 76.08,31.63 C179.1 ; C154.1 65.74,43.13 v1(65.81,43.21) 66.24,43.64 v1(68.53,43.64) ; v1(35.64,27.25) 35,27.89 28.32,27.89 26.4,29.81 26.4,30.95 26.19,31.17 25.04,31.17 23.29,32.92 19.3,32.92 17.24,34.97 17.24,36.96 15.95,38.25 15.95,49.72 16.03,49.8 17,50.77 18.1,50.77 21.31,50.77 21.47,50.94 v1(21.47,51.03)
  TOP w0.254: J2.145 48.17,60.37 47.96,60.15 v1(47.45,60.15) ; J2.69 69.17,60.46 69.06,60.35 v1(69.06,60.15) ; U8.10 v1(108.76,36.78) ; v1(43.08,60.25) 43.17,60.34 J2.165 v1(43.17,62.92) ; J2.121 56.17,62.4 56.54,62.76 56.9,62.76 56.92,62.74 v1(56.97,62.74) ; v1(105.71,42.67) 105.71,43.93 U8.33 ; v1(60.07,51.26) 59.92,51.41 J2.106 ; v1(122.53,82.75) 121.82,82.04 R28.1 ; D8.1 v1(129.11,80.57) ; J2.15 82.67,60.58 v1(83.12,60.13) ; R9.1 75.26,77.47 75.39,77.6 75.39,79.73 74.52,80.59 73.96,80.59 73.89,80.67 73.89,81.33 73.74,81.48 ; v1(9.09,45.92) 8.51,46.51 4.6,46.51 4.14,46.05 4.14,42.4 J16.14 4.14,40.56 4.14,34.4 J16.6 ; v1(110.31,44.4) 110.31,44.23 110.06,43.98 U8.25 ; D7.1 123.24,80.39 123.01,80.39 v1(122.89,80.26) ; U8.16 112.21,38.45 v1(112.24,38.48) ; v1(64.47,78.82) 64.41,78.77 64.41,77.55 64.92,77.04 D44.2 ; v1(31.7,54.94) 31.7,54.91 30.92,54.14 J2.214 ; v1(79.71,51.89) 79.32,51.89 78.92,52.29 J2.30 ; 19.1,45.25 J2.N2 ; J2.84 65.42,52.19 v1(65.37,52.14) ; v1(30.28,58.6) 30.02,58.85 30.02,60.25 30.17,60.4 J2.217 ; v1(116.51,40.59) 116.51,40.61 115.52,41.61 112.6,41.61 112.44,41.45 U8.22 ; C117.1 114.32,26.43 113.84,25.96 113.84,24.43 113.23,23.83 v1(112.47,23.83) ; J2.95 v1(62.67,62.64) ; v1(46.05,60.15) 46.42,60.15 46.67,60.4 J2.151 ; J2.56 72.42,52.19 v1(72.85,51.77) ; v1(106.76,36.75) U8.6 ; 35.64,54.58 v1(38.94,54.58)
  TOP w0.305: J14.11 v1(63.75,82.33) ; J20.22 36.46,7.86 v1(36.18,7.58) ; J14.14 v1(65.25,82.35) ; U8.37 102.11,42.45 101.8,42.76 v1(101.8,43) ; v1(86.16,63.94) Q14.2 ; Q15.2 82.85,64.62 82.63,64.83 82.16,64.83 81.71,65.28 v1(81.71,65.76) ; J14.2 v1(59.25,82.36) ; J14.8 v1(62.25,82.3) ; U8.40 103.86,40.95 104.22,40.59 104.22,39.3 v1(106.76,36.75) ; J14.17 66.75,82.2 v1(66.55,82.4) ; J14.5 v1(60.75,82.34)
  TOP w0.381: C57.1 114.95,37.22 114.38,37.8 v1(114,37.8) ; v1(121.06,30.18) 123.15,28.08 123.15,27.25 122.38,27.25 v1(120.6,29.03) ; J20.13 40.96,9.62 v1(40.84,9.73) 40.84,9.83 40.46,10.21 D104.8 D104.3 ; v1(105.49,70.31) 105.02,70.77 105.02,70.83 C31.1 104.1,71.13 v1(104.04,71.07) ; R277.1 66.46,38.2 v1(66.47,38.2) ; XT4.2 66.6,39.76 C153.1 65.34,39.76 65.23,39.65 v1(64.97,39.65) ; J2.N1 86.88,45.35 87.58,46.05 v1(87.58,48.08) ; J2.N1 86.24,45.35 85.42,46.18 v1(85.42,48.11) ; J2.N1 v1(86.6,48.08) ; R242.1 v1(31.09,33.99) ; v1(128.6,57.1) 128.6,57.1 D31.1 ; C56.1 99.32,38.67 v1(98.88,38.23) ; v1(120.29,66.17) 119.71,66.75 118.95,66.75 ; C176.2 62.81,33.88 v1(62.53,33.6) 62.88,33.26 C169.1 C168.2 ; v1(78.71,12.9) 78.56,12.75 D37.3 D37.8 ; v1(114.38,27.25) 114.39,27.24 XT2.4 ; v1(114.38,27.25) C117.1 ; v1(114.38,27.25) 114.38,27.89 114.76,28.27 118.72,28.27 119.1,27.89 119.1,26.5 XT2.2 118.04,24.44 v1(117.3,23.7) C114.2 116.6,23.51 115.27,22.17 113.64,22.17 v1(113.61,22.15) ; v1(24.08,25.22) R16.1 C23.1 24.47,26.54 v1(23.97,26.54) 23.98,26.55 23.98,27.13 24.14,27.29 C22.1 23.67,27.64 23.6,27.57 23.54,27.57 23.23,27.25 v1(22.94,27.25) ; C258.1 19.46,30.33 v1(19.63,30.51) ; v1(124.76,57.61) 124.76,58.01 C76.2 ; C79.1 72.69,15.93 v1(73.1,16.33) ; C190.1 105.99,48.77 v1(106.32,48.44) ; v1(43.38,37.54) 43.21,37.72 C133.1 R233.1 ; C95.1 77.01,50.28 v1(77.11,50.18) ; 28.27,3.78 J25.4 29.67,3.25 29.16,2.74 v1(28.27,2.74) ; v1(108.03,47.83) 107.77,47.57 C62.1 ; C66.1 124.87,63.65 D97.1 124.16,63.7 123.9,63.45 v1(123.44,63.45) ; v1(59.25,82.36) 59.12,82.5 58.5,82.5 58.12,82.12 v1(58.12,77.75) v1(58.12,73.99) ; v1(60.15,13.08) D98.3 D98.8 60.15,10.36 60.02,10.24 v1(60.02,9.72) J19.13 ; J5.A1 131.69,83.97 J5.H1 ; v1(26.03,16.03) 26.16,16.03 26.58,15.61 R120.1 ; v1(54.79,43.71) 54.7,43.63 54.7,43.32 C174.1 54.67,43.28 C167.1 ; J3.11 v1(97.2,77.45) ; J3.11 v1(98.49,76.27) ; J3.11 v1(97.2,75.16) ; C30.1 34,51.08 34.19,51.08 34.42,50.85 v1(34.44,50.85) ; C150.1 29.22,43.73 v1(29.06,43.89) ; v1(24.97,63.07) 25.35,63.45 C135.1 ; v1(132.41,80.66) C32.1 v1(131.62,79.86) ; J13.25 v1(81.04,9.73) ; U18.3 113.12,15.92 v1(113.36,16.15) ; v1(122.63,37.29) 122.56,37.36 C123.1 ; v1(55.83,63.45) 55.73,63.55 55.12,63.55 54.56,64.11 D5.1 D6.1 ; v1(93.14,58.98) 93.14,59.06 93.34,59.26 93.34,60.53 93.25,60.62 J26.55 91.96,59.56 v1(91.54,59.56) ; J25.3 24.71,3.78 ; J25.3 23.32,3 23.59,2.73 v1(24.7,2.73) ; J25.3 23.32,4.52 23.7,4.9 ; v1(81.36,20.55) 81.92,21.11 C82.1 C83.1 R100.1 ; C90.1 22.56,45.19 v1(22.3,45.44) 22.31,45.45 22.31,45.99 v1(22.23,46.08) ; D106.2 35.38,13.87 v1(35.03,14.22) 37.39,16.59 38.3,16.59 v1(38.68,16.97) ; v1(97.74,43.26) 97.99,43.26 98.37,42.88 C45.1 99.26,42.18 v1(99.26,42.01) ; R237.1 v1(34.04,33.99) ; D101.2 53.8,12.65 53.42,13.03 53.42,13.28 v1(53.04,13.67) ; D71.2 121.26,79.83 v1(120.8,80.29) ; J2.180 39.42,54.2 39.04,54.58 v1(38.94,54.58) ; J2.195 35.67,59.93 35.26,59.51 33.93,59.51 v1(33.91,59.54) ; R290.1 v1(55.83,31.45) ; 123.77,20.78 123.77,21.16 v1(123.9,21.29) ; 123.77,20.78 R60.1 ; 123.77,20.78 v1(123.27,21.29) ; C48.1 101.65,47.14 101.44,47.35 v1(100.1,47.35) ; v1(128.6,55.45) D30.1 ; v2(76.99,72.09) 76.43,72.09 D96.2 ; v1(54.69,36.4) 54.74,36.46 C162.1 ; v1(33.78,30.18) 33.98,29.98 C147.1 ; v1(15.21,64.54) 14.81,64.14 14.81,63.92 C4.1 ; C155.1 68.99,38.86 v1(69.15,38.7) 68.17,37.72 R271.1 ; C12.1 69.91,65.67 69.95,65.71 v1(69.98,65.71) 70,65.71 70.05,65.67 R5.1 70.75,65.67 71.34,66.26 71.34,66.37 71.62,66.65 ; v1(85.8,9.83) 85.54,9.57 J13.16 ; v1(79.49,9.69) 79.54,9.64 J13.28 ; v1(29.79,67.79) 29.44,67.44 D84.2 ; v1(26.47,42.82) 26.85,42.44 27.03,42.44 C143.1 ; 51.58,19.63 51.83,19.89 51.83,20.33 ; v1(21.06,44.65) 19.89,44.65 19.19,45.35 J2.N2 ; v1(39.7,30.12) 39.7,30.61 C136.1 39.55,30.74 38.96,30.15 ; C50.1 111.07,47.06 v1(111.07,47.83) ; C68.1 122.32,64.94 v1(122.1,64.72) ; v1(13.44,65.63) 13.44,64.53 C4.1 ; D36.2 77.55,15.57 v1(77.67,15.7) ; R81.2 121.62,74.63 v1(121.36,74.37) ; C61.1 104.54,31.95 v1(104.09,31.95) ; R273.1 66.29,35.59 v1(66.5,35.79) 66.06,36.23 R281.1 ; C77.2 124.98,59.32 v1(124.84,59.18) ; J26.43 v1(99.7,60.1) ; v1(87.83,9.86) 88.04,9.65 J13.11 ; C128.1 v1(97.49,23.7) ; C84.1 v1(94.44,21.58) ; C142.1 33.71,67.44 v1(33.73,67.42) 33.76,67.44 R213.2 ; XT3.2 43.37,40.47 v1(43.38,40.46) ; C60.1 108.73,32.14 v1(108.92,31.95) ; C25.1 C21.1 34.99,25.92 v1(34.8,25.73) ; R287.1 59.11,31.22 C171.1 59.42,32.01 v1(59.61,32.21) ; XT3.4 45.49,43.82 v1(46.18,43.13) ; v1(37.41,32.97) 37.29,33.1 C145.1 C144.1 36.65,32.08 v1(37.03,32.46) ; C54.1 98.27,38.03 v1(98.27,38.4) ; v1(58.45,51.49) 58.54,51.4 58.54,50.86 R421.1 58.42,50.74 57.73,50.74 C97.1 ; v1(94.06,73.48) 94.76,72.78 R45.1 ; v1(113.49,30.18) 113.48,30.18 113.48,30.75 XT1.2 ; v1(26.03,15.16) 25.88,15.16 25.44,15.61 R119.1 ; J5.H2 124.25,83.97 J5.A12 ; J19.10 v1(61.52,9.71) ; v1(122.5,70.18) 122.82,69.86 C249.1 C252.1 ; J13.37 v1(75.04,7.7) ; v1(72.44,70.03) 72.29,70.18 72,70.18 R6.1 ; v1(116.79,74.32) D28.1 ; R293.1 v1(54.81,31.45) ; J13.19 84.04,9.59 v1(84.28,9.83) 84.54,9.57 J13.18 ; v1(100.51,73.43) D3.8 D3.3 ; C104.1 C100.1 47.19,12.14 v1(47.45,12.4) ; v1(27.36,34.04) 26.19,34.04 24.21,36.02 D49.3 D49.8 ; J3.6 v1(107.3,77.17) ; v1(38.99,30.12) 38.96,30.15 ; 38.96,30.15 38.91,30.2 38.91,30.26 C137.1 38.33,30.64 v1(38.33,30.12) ; v1(109.17,11.76) 109.49,11.44 R201.2 ; C254.1 v1(66.62,13.41) ; C65.1 v1(128.73,62.69) 128.91,62.51 128.91,61.89 C63.2 ; C175.1 61.85,34.14 61.85,33.58 v1(61.87,33.55) ; v1(59.99,78.82) D40.8 D40.3 ; v1(9.42,60.17) 9.42,60.69 L1.3 ; R12.1 23.04,25.68 23.46,25.26 23.46,25.25 v1(23.4,25.19) ; R208.1 v1(99.73,18.66) ; v1(104.55,11.73) 104.06,12.23 U18.36 ; v1(59.66,33.5) 59.79,33.63 R284.1 ; D46.2 69.29,77.98 v1(69.37,77.9) 69.44,77.97 R108.1 ; v1(66.95,45.16) 66.76,45.36 R289.1 C173.1 ; v1(27.37,36.91) 27.34,36.88 26.64,36.88 24.84,38.68 D51.3 D51.8 ; v1(111.8,87.93) J3.12 111.15,86.62 v1(110.8,86.62) ; C59.1 114.95,40.14 114.68,40.41 v1(114.68,40.49) ; J26.27 v1(106.1,62.87) ; v1(124.87,56.34) 124.87,56.99 C74.2 ; J19.19 v1(57.02,9.78) 57.02,10.16 57.23,10.36 D99.8 D99.3 v1(57.23,13.08) ; C248.1 104.85,68.21 104.85,69.39 v1(104.65,69.6) ; v1(29.93,13.91) 29.4,14.44 U14.1 ; D27.1 120.6,74.63 v1(120.35,74.37) ; C98.1 v1(48.21,12.4) ; C58.1 v1(109.8,47.83) ; J26.29 v1(105.3,62.88) ; v1(104.22,47.83) 104.22,47.77 C55.1 ; v1(42.37,9.73) 42.46,9.64 J20.10 ; v1(125.55,23.01) 125.63,22.94 D65.2 ; v1(34.04,54.71) 34.06,54.69 35.54,54.69 35.92,54.31 J2.194 ; C80.1 75.13,13.29 76.28,12.14 76.28,9.98 v1(76.54,9.72) J13.34 ; v1(65.86,13.39) 65.61,13.13 C255.1 ; D35.8 D35.3 v1(81.23,12.9) ; J26.21 108.5,59.87 108.88,59.49 v1(109.47,59.49) ; D103.3 D103.8 v1(43.76,10.13) ; J26.4 118.5,52.19 v1(118.92,51.77) ; v1(111.8,77.33) J3.10 v1(111.8,75.13) ; v1(38.66,15.19) 38.38,14.91 D105.2 ; C4.1 14.43,63.58 13.94,64.06 13.94,64.14 v1(13.46,64.62) ; U25.3 v1(12.27,17.33) ; L1.3 v1(10.05,62.62) ; L1.3 v1(10.05,60.21) ; D34.8 D34.3 v1(92.41,12.78) ; v1(56.21,70.05) 55.06,70.05 54.68,69.67 J4.3 ; C243.1 15.49,11.71 ; 15.49,11.71 v1(17.73,11.71) ; 15.49,11.71 v1(16.43,12.65) ; D14.3 v1(84.63,71.32) ; v1(41.22,42.88) 40.79,43.31 C149.1 ; v1(30.05,33.99) 30.12,34.06 R245.1 ; v1(114.12,16.21) 114.41,15.92 C115.1 115.11,15.92 v1(115.39,16.21) ; v1(100.41,51.77) 100.9,52.26 J26.40 ; v1(79.68,74.22) 79.63,74.17 D107.8 ; v1(114.66,62.94) 114.1,62.38 J26.15 ; J26.26 v1(106.5,55.07) ; v1(61.57,48.95) 61.57,47.68 62.31,46.94 C164.2 ; C44.1 98.58,41.16 v1(98.58,42.01) ; v1(127.97,80.49) D12.1 ; v1(67.08,26.09) 67.08,25.97 67.33,25.72 U17.2 ; D53.2 23.9,41.96 24.51,41.35 v1(25.37,41.35) ; C126.1 v1(97.49,22.68) ; C127.1 97.64,27.36 96.82,27.36 v1(96.8,27.33) 97.4,27.33 97.4,27.15 97.64,27.15 97.82,26.97 97.82,26.86 C122.1 ; v1(42.49,40.59) 42.18,40.9 C130.1 ; C73.2 v1(124.98,54.81) ; v1(29.06,45.19) 30.81,46.94 v1(30.96,46.94) ; v1(55.68,9.75) 55.52,9.6 J19.22 ; C195.1 107.52,49.23 v1(107.9,48.84) ; v1(63.32,10.85) D102.8 D102.3 ; J2.31 78.67,60.49 v1(79.04,60.12) ; J19.16 v1(58.52,9.83) ; C85.1 72.48,77.05 72.52,77.01 73,77.5 v1(73,77.88) ; v1(26.52,43.38) 27.06,43.38 C148.1 ; C134.1 27.1,64.69 26.62,65.18 v1(26.62,65.23) ; v1(40.69,39.52) 40.67,39.52 R229.1 ; v1(125.5,80.48) 125.5,80.7 125.35,80.85 D9.1 ; C181.1 74.76,36.63 v1(74.85,36.73) ; R235.1 v1(33.1,33.99) ; D20.1 126.52,15.22 v1(126.85,15.54) ; v2(84.94,74.17) 84.63,73.86 D14.8 ; D25.1 101.95,6.35 v1(101.27,6.35) ; C151.1 C152.1 v1(36.91,33.99) ; D41.3 D41.8 v1(62.99,78.79) ; C96.1 66.75,15.95 v1(66.62,16.08) ; C217.1 43.19,35.38 v1(42.49,35.38) 42.11,35.38 40.97,36.53 40.97,37.54 40.39,38.13 R225.1 ; C166.1 51.06,67.44 52.13,68.51 J4.5 52.13,71.34 51.66,71.81 ; v1(95.11,25.08) 95.11,24.9 94.93,24.73 R101.1 ; J26.18 109.7,54.26 v1(109.27,54.69) ; D33.1 128.3,59.72 v1(128.6,60.02) ; J3.13 v1(96.3,84.32) ; J3.13 v1(96.3,87.49) ; J3.13 v1(95.16,85.97) ; J13.22 v1(82.54,9.73) ; v1(45.8,38.73) C131.1 ; J13.31 v1(78.04,9.71) ; C49.1 110.89,33.55 v1(112.09,34.75) ; v1(40.84,42.37) R241.1 C139.1 ; v1(70.18,70.03) 69.49,69.34 69.27,69.34 69.17,69.24 68.6,69.24 C7.1 68.52,69.22 68.38,69.07 68.38,67.34 v1(68.36,67.32) ; R239.1 v1(32.08,33.99) ; v1(96.01,14.2) C53.2 v1(96.77,14.92) ; v1(126.17,80.61) D10.1 ; D45.2 66.51,77.03 67.05,77.03 v1(67.06,77.04) 67.13,76.96 67.54,76.96 D47.2 ; C93.1 10.94,33.11 v1(10.26,33.78) ; C202.1 v1(108.66,48.84) ; U18.33 v1(100.03,14.12) ; v1(117.3,16.21) 117.61,15.89 C116.1 118.26,15.89 v1(118.57,16.21) ; R286.1 v1(57.86,33.6) ; D38.2 v1(76.28,15.7) ; C132.1 43.28,38.89 v1(43.36,38.81) ; C172.1 67.01,32.01 v1(67.01,31.95) 67.01,31 66.62,30.61 C160.1 65.66,30.61 v1(65.61,30.66) 65.56,30.61 C161.1 64.53,30.61 v1(64.21,30.94) ; C99.1 v1(45.92,14.43) ; D26.1 v1(103.73,6.2) ; D23.1 v1(113.08,6.27) ; U18.31 v1(100.06,15.92) ; v1(64.9,74.5) 64.92,74.48 C6.1 ; R179.1 v1(66.12,19.2) ; C120.1 98.74,26.91 98.74,26.98 98.54,27.18 98.47,27.18 98.41,27.24 98.09,27.24 v1(98.02,27.3) ; C253.1 v1(67.64,13.41) ; J26.35 102.9,62.38 v1(102.49,62.79) 102.1,62.4 J26.37 v1(102.1,60.07) ; R176.1 v1(59.89,19.38) ; v1(102.82,71.75) 102.97,71.61 D2.1 ; C209.1 118.06,49.79 C199.1 C200.1 ; D81.2 39.95,67.39 v1(40.34,67.77) ; v1(33.76,4.42) J20.26 v1(33.76,8.31) ; v1(33.91,13.51) 33.88,13.54 33.88,14.72 C94.1 ; U25.1 12.25,18.63 v1(12.4,18.49) ; D82.2 v1(46.81,67.39) ; C156.1 36.3,67.23 v1(36.78,66.75) ; 112.85,71.83 113.67,71.83 114.4,72.57 v1(114.4,72.69) ; C146.1 v1(35,33.99) ; J26.34 103.3,54.43 102.92,54.81 v1(102.31,54.81) ; D107.3 v1(79.63,71.35) ; XT4.4 68.79,43.37 v1(68.53,43.64) ; D4.3 D4.8 v1(107.01,73.48) ; v1(64.39,41.22) 64.39,41.28 64.85,41.73 64.85,41.86 65.55,42.56 C154.1 ; U15.2 v1(56.68,26.11) ; v1(58.12,48.95) 57.76,48.59 C165.1 ; v1(123.44,62.81) 123.44,62.15 122.55,61.26 J26.56 ; D17.3 v1(88.7,71.45) ; C140.1 32.21,45.69 v1(31.85,46.05) ; C121.1 v1(97.49,24.59) ; C129.1 41.46,43.83 v1(41.4,43.89) ; v1(98.04,73.1) D15.2 ; v1(60.76,33.6) C170.1 ; D52.2 23.6,40.56 24.08,40.08 25.65,40.08 v1(25.96,39.78) ; v1(55.12,13.16) 55.07,13.11 D100.2 ; v1(123.6,16) 123.8,16 124.59,15.22 D18.1 ; D32.1 v1(128.57,58.22) ; v1(95.4,8.26) 95.4,7.05 J13.41 95.39,6.39 96.34,7.34 v1(96.34,8.31) ; 118.95,71.83 v1(120.22,71.83) ; C78.1 v1(89.42,12.57) ; C81.1 93.44,17.33 v1(92.79,17.98) ; J26.9 v1(116.5,62.91) ; R102.1 v1(94.26,24.42) ; D17.8 v1(88.7,73.66) ; U18.20 v1(104.06,25.26) ; v1(109.55,64.34) 109.6,64.34 109.86,64.08 C71.1 ; C182.1 v1(122.19,76.91) ; R73.2 v1(108.79,47.83) ; R219.1 v1(45.8,39.83) ; U16.2 v1(61.8,26.14) ; v1(128.73,63.7) D29.1 ; D22.1 v1(114.38,6.3) ; J20.16 v1(39.46,9.63)
  TOP w0.508: U13.2 v1(29.54,17.42) ; 69.42,81.48 69.42,81.48 J14.20 ; v1(112.57,9.86) 112.12,10.31 R72.1 ; v1(26.9,23.13) C89.1 v1(28.02,23.13) C88.1
  TOP w0.61: LED1.2 73.74,84.91 ; LED1.2 73.74,83.13 ; LED1.2 74.63,84.02 ; LED1.2 72.85,84.02
  TOP w0.889: 79.87,75.21 J6.20 81.44,76.79 ; 5.89,33.48 J16.6 4.23,33.48 ; 104.91,3 J9.4 ; J9.4 105.69,3.78 ; J9.4 106.47,3 ; J8.4 117.49,3 ; J8.4 116.71,3.78 ; J8.4 115.93,3 ; J14.22 56,88.62 ; J14.22 56,86.26 ; J14.22 56.78,87.44 ; 133.55,53.3 J24.6 133.55,51.25 ; 133.55,28.39 J24.24 ; J24.24 133.55,30.44 ; J24.24 132.53,29.41 ; 132.29,86 J5.H1 133.06,84.57 ; 127.72,3.78 J7.4 126.95,3 ; 70.5,86.26 J14.23 ; J14.23 70.5,88.62 ; J14.23 71.28,87.44 ; J14.23 69.72,87.44 ; 82.52,15.05 J2.N3 ; J2.N3 85.2,12.38 ; J2.N3 87.88,15.05 ; 79.87,84.04 J6.21 78.29,82.47 ; J6.4 83.67,80.47 ; J6.4 82.2,80.47 ; J6.4 82.94,81.2 ; 4.23,63 J28.14 5.89,63 ; 7.89,33.48 J16.5 6.23,33.48 ; 123.65,87.54 J5.H4 ; J5.H4 122.97,88.72 ; J5.H4 124.32,88.72 ; 36.91,74.88 36.91,75.82 ; 36.91,74.88 37.85,74.88 ; 36.91,74.88 36.91,73.94 ; 132.29,87.54 J5.H3 ; J5.H3 132.96,88.72 ; J5.H3 131.61,88.72 ; 93.01,75.21 J6.19 93.01,78.36 ; 117.54,9.35 H1.1 ; H1.1 119.96,6.92 ; H1.1 119.96,11.78 ; 122.87,84.57 J5.H2 123.65,86 ; J14.21 56.78,81.48 ; J14.21 56,83.16 ; J14.21 56,79.8 ; 132.53,16.71 J24.34 ; J24.34 133.55,17.74 ; J24.34 133.55,15.69 ; J24.33 132.04,16.71 ; J24.33 131.01,15.69 ; J24.33 129.99,16.71 ; 91.43,82.47 J6.22 ; J6.22 94.58,82.47 ; J6.22 93.01,84.04 ; 11.86,45.08 H2.1 ; H2.1 8.58,48.36 ; H2.1 11.86,51.64 ; 90.52,29.68 J27.G4 88.1,27.25 ; 125.66,68.51 J11.2 ; J11.2 127.22,68.51 ; J11.2 126.44,67.74 ; 85.7,78.97 J6.7 ; J6.7 87.17,78.97 ; J6.7 86.44,79.7 ; 5.89,41.48 J16.14 4.23,41.48 ; 18.11,73.94 18.11,74.88 ; 18.11,74.88 19.05,74.88 ; 18.11,74.88 18.11,75.82
  L2-GND w0.889: 91.43,82.47 J6.22 ; J6.22 93.01,80.89 ; J6.22 94.58,82.47 ; J6.22 93.01,84.04 ; J16.5 7.06,34.16 ; J16.5 6.38,33.48 ; J16.5 7.74,33.48 ; 18.11,74.88 19.05,74.88 ; 18.11,74.88 18.11,73.94 ; 18.11,74.88 18.11,75.82 ; 132.53,52.27 J24.6 ; J24.6 133.55,51.25 ; J24.6 133.55,53.3 ; 104.91,3 J9.4 ; J9.4 105.69,3.78 ; J9.4 105.69,2.22 ; J9.4 106.47,3 ; 18.72,15.05 J2.N4 ; J2.N4 22.08,15.05 ; J2.N4 20.4,13.38 ; J2.N4 20.4,16.73 ; 131.01,51.25 J24.5 ; J24.5 132.04,52.27 ; J24.5 129.99,52.27 ; J24.5 131.01,53.3 ; 6.38,41.48 J16.13 ; J16.13 7.74,41.48 ; J16.13 7.06,40.8 ; J16.13 7.06,42.16 ; 122.97,88.72 J5.H4 ; J5.H4 123.65,87.54 ; J5.H4 124.32,88.72 ; J6.20 81.44,76.79 ; J6.20 79.87,78.36 ; J6.20 78.29,76.79 ; J6.20 79.87,75.21 ; 82.2,77.27 J6.13 83.67,77.27 ; 83.52,15.05 J2.N3 ; J2.N3 85.2,13.38 ; J2.N3 85.2,16.73 ; J2.N3 86.88,15.05 ; 72.85,81.48 73.74,81.48 ; 73.74,81.48 73.74,82.37 ; 73.74,81.48 73.74,80.59 ; 132.29,83.14 J5.H1 ; J5.H1 132.29,86 ; J5.H1 133.06,84.57 ; 5.06,52.33 J28.4 ; J28.4 5.06,53.68 ; J28.4 4.38,53 ; J28.4 5.74,53 ; J6.21 81.44,82.47 ; J6.21 78.29,82.47 ; J6.21 79.87,80.89 ; J6.21 79.87,84.04 ; 131.01,15.69 J24.33 ; J24.33 132.04,16.71 ; J24.33 129.99,16.71 ; J24.33 131.01,17.74 ; J8.4 117.49,3 ; J8.4 116.71,2.22 ; J8.4 115.93,3 ; J8.4 116.71,3.78 ; J7.4 127.72,3.78 ; J7.4 127.72,2.22 ; J7.4 126.95,3 ; J7.4 128.5,3 ; 9.18,48.36 H2.1 ; H2.1 11.86,51.04 ; H2.1 11.86,45.68 ; H2.1 14.54,48.36 ; J16.6 5.74,33.48 ; J16.6 4.38,33.48 ; J16.6 5.06,34.16 ; J14.23 70.5,88.62 ; J14.23 71.28,87.44 ; J14.23 70.5,86.26 ; J14.23 69.72,87.44 ; 123.65,86 J5.H2 122.87,84.57 ; J14.20 70.5,83.16 ; J14.20 69.72,81.48 ; J14.20 70.5,79.8 ; 36.91,74.88 36.91,75.82 ; 36.91,74.88 35.97,74.88 ; 36.91,74.88 36.91,73.94 ; 36.91,74.88 37.85,74.88 ; 133.55,28.39 J24.24 ; J24.24 133.55,30.44 ; J24.24 132.53,29.41 ; 88.6,27.25 J27.G4 ; J27.G4 92.45,27.25 ; J27.G4 90.52,25.33 ; J27.G4 90.52,29.18 ; 4.38,41.48 J16.14 ; J16.14 5.06,42.16 ; J16.14 5.74,41.48 ; J16.14 5.06,40.8 ; J11.2 127.22,68.51 ; J11.2 126.44,67.74 ; J11.2 126.44,69.29 ; J11.2 125.66,68.51 ; 86.44,78.23 J6.7 ; J6.7 87.17,78.97 ; J6.7 86.44,79.7 ; J6.7 85.7,78.97 ; J6.16 86.44,76.5 ; J6.16 87.17,75.77 ; J6.16 85.7,75.77 ; 82.2,80.47 J6.4 ; J6.4 83.67,80.47 ; J6.4 82.94,81.2 ; J6.19 93.01,78.36 ; J6.19 93.01,75.21 ; J6.19 94.58,76.79 ; J6.19 91.43,76.79 ; 118.29,9.35 H1.1 ; H1.1 119.96,7.67 ; H1.1 121.64,9.35 ; H1.1 119.96,11.03 ; 133.55,15.69 J24.34 ; J24.34 133.55,17.74 ; J24.34 132.53,16.71 ; 56,86.26 J14.22 ; J14.22 56,88.62 ; J14.22 56.78,87.44 ; J5.H3 132.96,88.72 ; J5.H3 131.61,88.72 ; J5.H3 132.29,87.54 ; 72.85,84.02 LED1.2 ; LED1.2 73.74,83.13 ; LED1.2 74.63,84.02 ; LED1.2 73.74,84.91
  L3-POW w0.889: J28.13 7.74,63 ; J28.13 7.06,62.33 ; J28.13 6.38,63 ; 72.85,81.48 73.74,81.48 ; 73.74,81.48 73.74,82.37 ; 73.74,81.48 73.74,80.59 ; 126.44,67.74 J11.2 ; J11.2 127.22,68.51 ; J11.2 126.44,69.29 ; J11.2 125.66,68.51 ; 126.95,3 J7.4 ; J7.4 127.72,2.22 ; J7.4 127.72,3.78 ; J7.4 128.5,3 ; J14.21 56.78,81.48 ; J14.21 55.22,81.48 ; J14.21 56,79.8 ; J14.21 56,83.16 ; 5.06,40.8 J16.14 ; J16.14 5.06,42.16 ; J16.14 5.74,41.48 ; J24.5 131.01,53.3 ; J24.5 131.01,51.25 ; J24.5 132.04,52.27 ; J24.5 129.99,52.27 ; 122.87,84.57 J5.H2 123.65,86 ; LED1.2 73.74,84.91 ; LED1.2 73.74,83.13 ; LED1.2 72.85,84.02 ; LED1.2 74.63,84.02 ; J27.G3 123.72,29.18 ; J27.G3 125.65,27.25 ; J27.G3 121.8,27.25 ; J27.G3 123.72,25.33 ; H1.1 119.96,11.03 ; H1.1 121.64,9.35 ; H1.1 118.29,9.35 ; 78.29,76.79 J6.20 ; J6.20 79.87,78.36 ; J6.20 79.87,75.21 ; J6.20 81.44,76.79 ; 129.99,16.71 J24.33 ; J24.33 131.01,15.69 ; J24.33 131.01,17.74 ; J24.33 132.04,16.71 ; 122.97,88.72 J5.H4 ; J5.H4 124.32,88.72 ; J5.H4 123.65,87.54 ; J14.22 56.78,87.44 ; J14.22 56,88.62 ; J14.22 55.22,87.44 ; J14.22 56,86.26 ; 116.71,2.22 J8.4 ; J8.4 115.93,3 ; J8.4 117.49,3 ; 133.55,28.39 J24.24 ; J24.24 133.55,30.44 ; J24.24 132.53,29.41 ; J6.21 79.87,84.04 ; J6.21 79.87,80.89 ; J6.21 78.29,82.47 ; J6.21 81.44,82.47 ; 36.91,74.88 36.91,75.82 ; 36.91,74.88 36.91,73.94 ; 36.91,74.88 37.85,74.88 ; 36.91,74.88 35.97,74.88 ; 132.29,83.14 J5.H1 ; J5.H1 133.06,84.57 ; J5.H1 132.29,86 ; 93.01,75.21 J6.19 ; J6.19 94.58,76.79 ; J6.19 91.43,76.79 ; J6.19 93.01,78.36 ; 82.2,80.47 J6.4 ; J6.4 82.94,81.2 ; J6.4 83.67,80.47 ; 7.06,40.8 J16.13 ; J16.13 7.06,42.16 ; J16.13 6.38,41.48 ; 85.7,75.77 J6.16 ; J6.16 87.17,75.77 ; J6.16 86.44,76.5 ; 82.2,77.27 J6.13 83.67,77.27 ; 9.18,48.36 H2.1 11.86,51.04 ; 5.06,62.33 J28.14 5.74,63 ; 5.06,52.33 J28.4 ; J28.4 5.06,53.68 ; J28.4 5.74,53 ; J2.N3 85.2,16.73 ; J2.N3 86.88,15.05 ; J2.N3 83.52,15.05 ; J2.N3 85.2,13.38 ; 132.29,87.54 J5.H3 ; J5.H3 132.96,88.72 ; J5.H3 131.61,88.72 ; 18.72,15.05 J2.N4 ; J2.N4 20.4,13.38 ; J2.N4 20.4,16.73 ; J2.N4 22.08,15.05 ; J16.6 5.74,33.48 ; J16.6 5.06,34.16 ; J16.6 5.06,32.8 ; 93.01,80.89 J6.22 ; J6.22 91.43,82.47 ; J6.22 93.01,84.04 ; J6.22 94.58,82.47 ; 133.55,51.25 J24.6 ; J24.6 133.55,53.3 ; J24.6 132.53,52.27 ; 90.52,25.33 J27.G4 ; J27.G4 90.52,29.18 ; J27.G4 88.6,27.25 ; J27.G4 92.45,27.25 ; J14.23 71.28,87.44 ; J14.23 69.72,87.44 ; J14.23 70.5,88.62 ; J14.23 70.5,86.26 ; 70.5,79.8 J14.20 ; J14.20 70.5,83.16 ; J14.20 69.72,81.48 ; J16.5 7.06,34.16 ; J16.5 6.38,33.48 ; J16.5 7.06,32.8 ; 18.11,74.88 18.11,75.82 ; 18.11,74.88 17.17,74.88 ; 18.11,74.88 19.05,74.88 ; 18.11,74.88 18.11,73.94 ; 133.55,15.69 J24.34 ; J24.34 133.55,17.74 ; J24.34 132.53,16.71 ; J9.4 106.47,3 ; J9.4 104.91,3 ; J9.4 105.69,2.22 ; 85.7,78.97 J6.7 ; J6.7 86.44,78.23 ; J6.7 87.17,78.97 ; J6.7 86.44,79.7
  BOTTOM w0.127: 18.8,64.64 18.26,65.18 18.26,67.34 v1(17.84,67.75) 17.4,68.2 15.31,68.2 15.21,68.09 D79.2 ; v1(22.74,56.4) 22.82,56.32 22.82,55.17 22.78,55.13 22.78,54.72 22.78,54.3 23.04,54.04 23.04,45.11 22.06,44.13 22.06,43.65 21.92,43.51 21.92,26.57 23.29,25.2 23.4,25.2 v1(23.4,25.19) 23.52,25.19 23.55,25.22 v1(24.08,25.22) 24.08,24.59 23.19,23.7 23.19,22.81 22.17,21.79 22.17,18.49 23.39,17.27 23.39,14.22 24.92,12.7 26.19,12.7 28.73,10.16 28.73,8.13 28.78,8.08 28.78,8.06 30.54,6.3 30.56,6.3 30.62,6.24 34.56,6.24 37.41,3.38 71.07,3.38 72.59,4.9 91.21,4.9 91.48,5.17 96.99,5.17 97,5.18 97.36,5.18 98.7,6.53 99,6.82 100.07,6.82 100.08,6.83 100.25,6.83 100.38,6.97 100.38,7.13 100.59,7.34 100.74,7.34 100.86,7.47 100.86,9.4 100.28,9.98 100.28,13.86 v1(100.03,14.12) 100.08,14.17 100.08,18.31 v1(99.73,18.66) 98.25,20.14 97.23,20.14 96.98,19.89 96.98,19.38 99.26,17.09 99.26,13.28 99.77,12.78 99.77,9.73 100.36,9.14 100.36,7.94 100.14,7.72 100.14,7.6 99.86,7.33 98.79,7.33 98.2,6.74 97.15,5.69 96.79,5.69 96.78,5.68 91.05,5.68 90.78,5.41 72.29,5.41 71.02,4.14 v1(68.78,4.14) v1(66.5,4.14) v1(61.42,4.14) v1(56.72,4.14) v1(52.4,4.14) v1(48.72,4.14) v1(45.16,4.14) v1(41.35,4.14) v1(37.8,4.14) 37.41,4.14 34.75,6.81 30.75,6.81 29.29,8.27 29.29,10.87 28.41,11.75 28.24,11.75 27.96,12.04 27.96,12.2 v1(27.89,12.27) 27.51,12.27 26.49,13.28 25.22,13.28 23.95,14.55 23.95,17.6 22.81,18.75 22.81,21.67 23.95,22.81 23.95,23.57 24.84,24.46 24.84,25.91 24.21,26.54 v1(23.97,26.54) 23.97,26.55 23.27,27.25 v1(22.94,27.25) 22.83,27.36 22.71,27.36 22.43,27.64 22.43,43.26 22.57,43.4 22.57,43.9 23.55,44.88 23.55,54.25 23.28,54.51 23.28,54.91 23.57,55.2 23.57,55.22 23.65,55.3 v1(23.65,55.4) ; 51.59,59.21 51.23,58.85 v1(50.06,58.85) 50.04,58.88 v1(48.79,58.88) v1(47.37,58.88) v1(46.05,58.88) 46,58.93 v1(44.55,58.93) 44.3,58.67 43.28,58.67 43.05,58.9 v1(43.05,58.95) 43.08,58.98 v1(43.08,60.25) 43.08,61.8 43.87,62.59 43.87,65.71 44.86,66.7 47.93,66.7 49.07,67.84 49.07,69.24 48.16,70.15 43.56,70.15 42.14,68.73 38.76,68.73 38.23,68.2 38.23,67.46 39.45,66.24 39.45,57.78 41.55,55.68 51.82,55.68 51.9,55.59 52.34,55.59 52.91,56.16 56.41,56.16 56.72,55.85 v1(56.72,55.5) 56.72,54.58 v1(56.67,54.53) 55.91,53.77 55.91,52.76 55.55,52.4 52.4,52.4 51.99,51.99 51.99,51.74 ; 51.59,59.21 51.66,59.13 58.37,59.13 60.91,56.59 60.91,54.46 62.15,53.21 62.15,49.53 v1(61.57,48.95) ; 51.59,59.21 52.17,59.79 52.17,60.2 55.3,63.32 55.7,63.32 v1(55.83,63.45) 56.21,63.83 61.19,63.83 61.19,63.84 61.25,63.84 69.15,71.74 75.3,71.74 75.72,71.32 75.72,71.02 76.68,70.05 84.2,70.05 85.98,68.28 92.79,68.28 v1(94.59,70.08) ; v1(40.87,47.83) 40.97,47.83 41.4,47.4 43.31,47.4 43.76,46.94 49.65,46.94 51.48,48.77 52.11,48.77 52.11,48.77 52.43,48.77 52.74,48.77 52.95,48.77 54.15,48.77 56.21,46.71 63.98,46.71 64.59,47.32 64.59,63.83 67.13,66.37 67.39,66.37 v1(67.56,66.55) 67.59,66.55 67.89,66.84 67.89,66.87 67.93,66.92 67.96,66.92 v1(67.97,66.93) 67.97,66.95 68.25,67.23 68.28,67.23 v1(68.36,67.32) 68.43,67.26 68.61,67.26 69.14,67.79 69.72,67.79 70.21,68.28 83.24,68.28 85.01,66.5 93.68,66.5 94.72,67.54 96.7,67.54 97.43,68.28 100.43,68.28 100.5,68.35 100.53,68.35 100.57,68.39 100.57,68.39 100.63,68.45 105.26,68.45 105.27,68.44 105.65,68.44 105.66,68.45 105.71,68.45 105.99,68.73 105.99,69.93 105.61,70.31 v1(105.49,70.31) 105.08,69.9 104.95,69.9 v1(104.65,69.6) 104.27,69.22 101.55,69.22 100.48,70.28 97.13,70.28 96.9,70.05 96.14,70.05 v1(96.11,70.08) ; v1(40.84,42.37) 40.67,42.19 39.52,42.19 39.22,42.49 38.79,42.49 38.28,41.99 38.28,37.24 37.9,36.86 37.9,35.74 36.91,34.75 v1(36.91,33.99) ; v1(70.92,54.56) 70.69,54.79 70.69,57.48 71.81,58.6 71.81,61.14 72.21,61.54 72.21,62.31 72.85,62.94 72.85,63.4 v1(73.03,63.58) ; v1(70.92,54.56) 71.42,55.07 71.96,55.07 72.21,54.81 72.21,54.31 70.69,52.78 70.69,43 67.89,40.21 67.89,38.3 67.41,37.82 66.88,37.82 66.5,38.2 v1(66.47,38.2) ; v1(70.92,54.56) 70.92,54.15 70.18,53.42 70.18,43.32 67.39,40.53 67.39,39.24 66.66,38.52 66.66,38.39 v1(66.47,38.2) ; 59.26,38.3 65.51,38.3 66.88,39.67 66.88,40.84 69.67,43.64 69.67,53.8 70.18,54.31 70.18,57.73 71.3,58.85 71.3,61.39 71.7,61.8 71.7,63.35 v1(72.06,63.7) ; 59.26,38.3 56.34,38.3 v1(56.24,38.2) ; 59.26,38.3 v1(58.75,38.81) ; v1(27.36,34.04) 27.36,33.76 27.23,33.63 27.23,32.41 27.53,32.11 27.91,32.11 28.35,32.54 28.57,32.54 29.01,32.97 35.89,32.97 ; J6.13 82.46,76.79 J6.20 77.9,76.79 77.9,76.94 76.96,77.88 ; v1(27.37,36.91) 27.37,37.12 27.13,37.36 27.13,38.18 27.64,38.68 v1(27.86,38.68) 27.86,39.12 28.78,40.03 29.06,40.03 v1(29.18,40.16) ; v1(19.86,34.49) 19.94,34.42 20.65,34.42 20.9,34.67 20.9,41.61 20.9,41.61 20.9,41.86 20.68,42.09 19.99,42.09 v1(19.79,41.88) ; v1(29.18,40.16) 29.41,39.93 29.41,38.43 30.56,37.29 31.22,37.29 v1(31.47,37.54) ; v1(29.18,40.16) 29.41,40.39 29.41,43.54 v1(29.06,43.89) 29.41,44.25 29.41,45.16 28.17,46.41 28.17,49.28 29.9,51 29.9,52.76 31.7,54.56 v1(31.7,54.94) 32.08,54.94 33.91,56.77 v1(33.91,58.29) ; v1(50.48,50.23) 50.49,50.23 51.03,50.77 51.03,51.32 51.3,51.6 51.69,51.6 51.77,51.51 51.99,51.74 ; 76.78,78.05 73.18,78.05 v1(73,77.88) 72.77,77.65 69.62,77.65 v1(69.37,77.9) 69.11,77.65 67.66,77.65 v1(67.06,77.04) 66.42,76.41 66.42,75.39 65.53,74.5 v1(64.9,74.5) ; 76.78,78.05 76.96,77.88 ; 76.78,78.05 76.96,77.88 ; v1(63.55,16.74) 64.54,17.73 71.2,17.73 79.58,26.11 80.34,26.11 81.36,27.13 v1(81.36,27.38) ; v1(43.76,10.13) 43.54,10.36 41.22,10.36 39.83,11.76 39.19,11.76 38.84,12.12 38.84,13.92 39.12,14.2 40.28,14.2 40.84,14.76 41.73,14.76 41.99,14.5 v1(41.99,14.15) 42.21,13.92 51.92,13.92 52.4,14.4 v1(52.4,16.94) 52.15,16.69 52.15,15.57 51.49,14.92 48.55,14.92 48.42,14.79 48.42,14.5 48.13,14.22 47.73,14.22 47.44,14.5 47.44,14.79 47.31,14.92 44.16,14.92 43.51,15.57 40.21,15.57 39.67,15.04 38.81,15.04 v1(38.66,15.19) ; v1(90.4,35.51) 90.4,35.99 89.99,36.4 88.24,36.4 85.06,33.22 81.36,33.22 80.34,32.21 79.07,32.21 v1(78.69,31.83) 78.56,31.7 78.56,31.22 69.9,22.56 56.72,22.56 53.67,19.51 53.67,18.36 53.42,18.11 v1(53.42,17.91) 53.54,17.78 53.54,16.97 53.04,16.46 v1(53.04,13.67) 52.78,13.41 41.22,13.41 40.63,14.01 v1(40.47,14.01) ; v1(52.04,24.26) 53.14,25.35 53.75,25.35 54.8,25.35 55.37,25.35 68.58,25.35 72.8,29.56 72.8,30.51 78.44,36.14 84.15,36.14 84.4,36.4 85.14,36.4 85.7,35.84 v1(85.7,35.81) 85.29,35.41 84.76,35.41 84.56,35.61 78.66,35.61 73.36,30.3 73.36,29.4 68.79,24.84 68.58,24.84 68.58,24.84 55.16,24.84 54.59,24.84 54.59,24.84 53.96,24.84 53.8,24.84 52.25,23.29 v1(52.04,23.29) ; v1(72.44,70.03) 72.26,69.85 70.46,69.85 70.28,70.03 v1(70.18,70.03) ; v1(42.34,22.53) 42.57,22.3 43.05,22.3 44.4,23.65 44.4,26.14 44.07,26.47 v1(43.46,26.47) ; v1(33.78,30.18) 33.6,30.18 32.64,29.21 27.25,29.21 25.02,31.45 25.02,40.61 25.22,40.82 26.01,41.61 26.49,41.61 26.49,42.8 v1(26.47,42.82) ; 120.65,64.24 121.03,63.86 121.03,59.74 123.52,57.25 123.52,55.19 125.93,52.78 125.93,51.64 125.43,51.13 125.43,50.6 126.19,49.83 v1(126.19,49.68) 126.44,49.94 126.44,53.35 v1(124.98,54.81) 124.03,55.76 124.03,57.48 121.64,59.87 121.64,64.06 121.34,64.36 121.34,68.14 118.66,70.82 113.23,70.82 112.34,69.93 110.31,69.93 107.01,66.62 102.69,66.62 101.8,65.74 95.55,65.74 94.28,64.47 v1(93.65,64.47) ; v1(31.47,37.54) 31.47,37.77 29.92,39.32 29.92,45.42 28.68,46.66 28.68,49.02 30.4,50.75 30.4,52.5 34.52,56.62 34.52,57.71 35,58.19 35,63.07 33.88,64.19 27.84,64.19 27.81,64.21 27.64,64.21 v1(26.62,65.23) ; v1(31.47,37.54) 31.8,37.54 32,37.34 32.54,37.34 33.5,38.3 33.5,39.04 v1(33.48,39.07) ; v1(66.6,60.17) 66.6,60.2 66.52,60.27 66.52,61.8 ; v1(94.93,45.33) 94.84,45.42 85.53,45.42 81.99,48.95 81.99,57.35 79.97,59.37 79.97,59.78 79.63,60.12 v1(79.04,60.12) 78.94,60.02 78.94,57.86 79.98,56.83 C112.1 ; v1(80.34,27.2) 79.91,27.2 70.94,18.24 63.96,18.24 62.43,16.71 v1(62.18,16.71) ; 66.52,61.8 68.02,61.8 68.38,62.15 68.38,62.66 68.26,62.78 68.26,62.99 68.22,63.04 68.22,63.07 68.15,63.14 68.15,63.37 68.99,64.21 69.55,64.21 71.32,65.99 81.48,65.99 v1(81.71,65.76) 81.94,65.53 82.52,65.53 84.11,63.94 v1(86.16,63.94) 86.4,64.19 87.76,64.19 88.21,63.73 94.31,63.73 95.81,65.23 102.06,65.23 102.95,66.12 107.24,66.12 110.54,69.42 112.7,69.42 113.56,70.28 118.44,70.28 120.83,67.89 120.83,66.65 120.35,66.17 v1(120.29,66.17) ; 66.52,61.8 66.52,62.53 68.83,64.85 69.09,64.85 69.95,65.71 v1(69.98,65.71) 70.28,65.71 71.07,66.5 82.32,66.5 84.12,64.69 88.01,64.69 88.44,64.26 92.05,64.26 v1(92.25,64.47) ; v1(66.47,38.2) 66.07,37.8 57.81,37.8 v1(57.58,37.57) ; 24.84,41.45 24.69,41.61 24.69,42.2 24.82,42.33 24.82,42.34 24.87,42.39 24.87,43.13 25.81,44.07 25.81,50.11 27.64,51.94 27.64,54.18 27.89,54.43 27.89,55.19 27.56,55.52 v1(27.51,55.52) 27.5,55.53 27.21,55.53 26.87,55.19 26.87,52.04 25.22,50.39 25.22,44.29 24.18,43.25 24.18,31.52 27.18,28.52 32.85,28.52 33.79,29.46 34.41,29.46 36.27,31.32 36.27,31.83 v1(37.41,32.97) ; v1(93.24,44.6) 93.24,44.78 93.12,44.91 85.27,44.91 81.59,48.59 v1(79.83,48.59) 79.83,51.77 v1(79.71,51.89) ; v1(49.86,49.61) 49.43,49.19 48.78,49.19 48.3,48.72 44.93,48.72 43.57,50.08 41.36,50.08 39.73,48.44 39.73,44.45 41.22,42.95 v1(41.22,42.88) ; 115.7,54.1 116.23,54.1 116.48,54.36 116.48,54.76 116.13,55.12 115.98,55.12 115.49,55.6 115.65,55.75 115.65,58.37 116.87,59.59 116.87,61.85 116.5,62.21 v1(116.5,62.91) 116.49,62.92 115.75,62.92 114.86,63.8 114.86,65.53 v1(115.11,65.79) 114.78,66.12 v1(114.1,66.12) 114.1,66.04 113.79,65.74 113.79,63.88 114.66,63.02 v1(114.66,62.94) ; v1(106.27,71.17) 106.63,70.82 106.63,69.29 106.5,69.16 106.5,68.48 105.92,67.89 100.79,67.89 100.66,67.77 97.69,67.77 96.95,67.03 94.97,67.03 93.9,65.96 84.79,65.96 82.98,67.77 70.46,67.77 69.95,67.26 69.37,67.26 67.11,65 66.78,65 65.1,63.32 65.1,52.4 65.36,52.14 v1(65.37,52.14) 65.13,51.89 65.13,47.09 64.21,46.18 56.03,46.18 53.94,48.26 52.74,48.26 52.53,48.26 52.22,48.26 51.9,48.26 51.69,48.26 49.86,46.43 43.24,46.43 42.8,46.87 41.58,46.87 41.27,46.57 41.14,46.57 v1(40.89,46.81) ; v1(58.12,48.95) 57.71,48.54 56.9,48.54 54.86,50.57 52.22,50.57 51.99,50.8 51.99,51.74 ; 57.23,15.54 57,15.77 57,16.61 v1(57.02,16.64) 57.02,16.92 56.67,17.27 v1(56.67,19) ; v1(59.66,33.5) 60.05,33.5 60.15,33.6 v1(60.76,33.6) 60.78,33.6 62.31,35.13 62.31,35.76 62.81,36.27 68.15,36.27 69.93,38.05 69.93,38.35 72.21,40.64 72.21,49.86 73.74,51.38 73.74,51.64 v1(73.89,51.79) 73.89,52.43 74.63,53.16 74.63,58.37 76.1,59.84 76.1,60.3 75.84,60.55 75.44,60.55 74.12,59.23 74.12,53.42 72.85,52.15 v1(72.85,51.77) 71.7,50.62 71.7,42.49 69.15,39.94 v1(69.15,38.7) 69.15,38.04 67.89,36.78 62.56,36.78 61.8,36.02 61.8,35.38 60.78,34.37 59,34.37 58.24,33.6 v1(57.86,33.6) ; v1(29.03,56.34) 29.16,56.21 29.16,55.7 28.65,55.19 28.65,53.92 28.33,53.61 28.33,51.78 26.59,50.04 26.59,45.69 27.25,45.03 27.25,41.1 25.96,39.8 v1(25.96,39.78) 25.58,39.4 25.58,31.65 27.3,29.92 32.18,29.92 33.6,31.34 33.6,31.7 33.86,31.95 34.37,31.95 34.79,31.53 ; v1(38.68,16.97) 39.57,16.97 40.21,16.33 43.89,16.33 44.55,15.67 51.1,15.67 51.38,15.95 51.38,17.37 51.79,17.78 51.79,19.13 52.02,19.13 v1(52.53,19.63) 52.65,19.63 56.34,23.32 67.95,23.32 67.95,23.32 69.43,23.32 69.43,23.32 69.6,23.32 77.55,31.27 77.55,32.21 78.31,32.97 80.04,32.97 81.05,33.99 84.76,33.99 87.96,37.19 90.35,37.19 90.73,36.8 v1(91.95,36.8) ; v1(116,59.97) 116,59.56 115.42,58.98 ; v1(83.12,60.13) 83.12,59.78 84.66,58.24 84.66,52.91 83.52,51.77 83.52,49.73 85.14,48.11 v1(85.42,48.11) 85.42,47.83 85.8,47.45 93.98,47.45 94.64,46.79 v1(94.64,47.04) ; v1(52.48,55.32) 52.48,54.89 52.15,54.56 v2(51.51,54.56) 51.41,54.46 50.44,54.46 50.06,54.84 39.19,54.84 v1(38.94,54.58) 38.38,55.14 38.38,56.01 38.81,56.44 38.81,66.09 36.5,68.4 33.15,68.4 32.79,68.76 28.17,68.76 v1(27.81,68.4) 27.41,68.81 21.59,68.81 21.21,68.43 21.21,67.34 22.35,66.19 25.1,66.19 25.3,65.99 v1(25.35,65.99) v1(26.11,65.99) 26.42,65.68 28.4,65.68 29.13,64.95 34.67,64.95 35.76,63.86 35.76,57.78 35.28,57.3 35.28,55.8 34.19,54.71 v1(34.04,54.71) 31.19,51.87 31.19,48.46 30.71,47.98 30.71,47.17 30.94,46.94 v1(30.96,46.94)
  BOTTOM w0.203: v1(128.73,62.69) 128.73,61.67 129.87,60.53 129.87,48.59 128.85,47.57 128.85,39.95 126.57,37.67 123.01,37.67 v1(122.63,37.29) 122.25,37.67 115.57,37.67 113.47,35.57 112.69,35.57 112.09,34.98 v1(112.09,34.75) 111.84,34.75 110.31,33.22 101.93,33.22 100.89,32.18 100.81,32.18 100.54,32.46 98.19,32.46 97.74,32 v1(97.69,32) ; v1(128.6,60.02) 127.97,60.02 125.93,62.05 125.93,63.83 126.31,64.21 ; 34.79,31.24 33.78,30.23 v1(33.78,30.18) ; 34.79,31.24 35.08,31.53 ; 34.79,31.24 34.79,31.53 35.08,31.53 ; v1(27.91,56.46) 27.91,55.93 v1(27.51,55.52) ; v1(34.8,25.73) 35.26,25.27 35.26,14.4 35.08,14.22 v1(35.03,14.22) 34.9,14.1 34.9,8.99 36.18,7.71 v1(36.18,7.58) 36.33,7.58 38.23,5.69 70.46,5.69 77.5,12.73 77.5,15.52 v1(77.67,15.7) 77.52,15.85 77.52,16.94 81.13,20.55 v1(81.36,20.55) 81.36,20.78 86.08,25.5 v1(86.44,25.5) 86.5,25.56 86.5,25.92 87.07,26.49 87.07,26.82 v1(86.97,26.92) 87.07,27.03 87.07,27.38 88.18,28.49 88.18,29.18 88.38,29.39 v1(88.42,29.39) 88.57,29.54 89.23,29.54 89.99,30.3 91.87,30.3 v1(92.28,29.9) ; v1(128.6,55.45) v1(128.6,51.23) v1(128.6,49.99) 128.6,48.84 127.71,47.96 127.71,40.34 126.19,38.81 115.01,38.81 v1(114,37.8) 113.87,37.8 112.85,36.78 112.34,36.78 109.8,34.24 101.42,34.24 100.71,33.53 97.05,33.53 94.97,31.45 89.61,31.45 88.77,30.61 87.88,30.61 87.12,29.84 87.12,28.96 85.67,27.51 85.67,26.62 76.28,17.22 v1(76.28,16.71) v1(76.28,15.7) 76.28,15.7 76.28,13.03 70.05,6.81 38.96,6.81 v1(37.99,7.79) 37.76,7.79 35.94,9.6 35.94,13.21 36.3,13.56 36.3,26.01 35.74,26.57 35.74,27.15 v1(35.64,27.25) ; 35.08,31.53 35.38,31.83 35.38,32.46 v1(36.91,33.99) 37.67,33.99 39.32,35.64 39.32,38.3 40.54,39.52 v1(40.69,39.52) 41,39.83 44.53,39.83 44.72,39.64 44.72,39 44.4,38.68 43.48,38.68 v1(43.36,38.81) 43.1,39.07 41.33,39.07 40.84,38.58 40.84,38.18 J27.G2 40.53,37.6 39.95,37.03 39.95,35.26 37.67,32.97 v1(37.41,32.97) ; 126.82,55.83 127.03,56.03 127.03,58.95 124.61,61.37 124.61,64.01 124.03,64.59 124.03,68.53 124.61,69.11 124.61,71.58 123.39,72.8 122.71,72.8 121.74,71.83 ; 126.82,55.83 127.04,55.61 127.04,49.31 126.31,48.59 126.31,40.97 125.63,40.28 116.81,40.28 v1(116.51,40.59) 116.38,40.46 114.71,40.46 v1(114.68,40.49) 114.02,40.49 112.24,38.7 v1(112.24,38.48) 112.21,38.45 111.98,38.45 109.25,35.71 100.91,35.71 100.48,35.28 93.45,35.28 v1(93.01,34.85) ; 126.82,55.83 125.27,55.83 124.87,56.24 v1(124.87,56.34) 124.92,56.39 124.92,57.35 124.76,57.51 v1(124.76,57.61) 124.71,57.61 122.25,60.07 122.25,64.57 v1(122.1,64.72) 122.1,68.15 118.87,71.37 112.93,71.37 112.09,70.54 108.56,70.54 108.15,70.94 108.15,72.47 108.41,72.72 109.68,72.72 110.57,71.83 111.81,71.83 112.5,72.52 114.22,72.52 v1(114.4,72.69) ; 17.31,33.01 v1(15.72,33.01) 15.28,33.01 15.24,33.05 15.14,33.05 15.14,33.05 v1(15.05,33.05) ; v1(92.05,33.73) 92.05,33.12 91.77,32.84 90.22,32.84 90.07,32.99 v1(89.15,32.99) 88.32,32.16 v1(87.48,32.16) 87.4,32.08 87.2,32.08 85.7,30.58 v1(85.65,30.58) 85.65,30.56 85.8,30.4 85.8,29.79 85.39,29.39 v1(84.96,29.39) 84.96,28.83 84.53,28.4 v1(84.02,28.4) 84.05,28.37 v1(84.05,27.53) 84.05,27.03 75.26,18.24 v1(75.01,18.24) 75.01,17.98 74.63,17.6 74.63,16.89 74.42,16.69 74.27,16.69 ; 74.27,16.69 74.63,16.33 74.63,13.54 69.29,8.2 53.92,8.2 v1(53.67,8.46) 53.43,8.22 53.15,8.22 v1(52.91,8.46) 52.67,8.22 52.38,8.22 v1(52.15,8.46) 51.91,8.22 51.62,8.22 v1(51.38,8.46) 51.13,8.2 39.75,8.2 38.58,9.37 38.15,9.37 37.31,10.21 37.31,12.55 37.67,12.9 37.67,26.37 37.71,26.4 37.71,26.45 37.79,26.54 37.79,27.07 37.8,27.07 v1(37.8,27.25) ; 74.27,16.69 v1(73.79,16.69) ; v1(124.84,59.18) 123.44,60.58 v1(123.44,62.81) v1(123.44,63.45)
  BOTTOM w0.254: D79.2 14.09,68.09 13.99,68.2 12.09,68.2 10.31,69.98 4.7,69.98 3.75,69.02 3.75,64.32 J28.14 5.06,63 3.76,61.7 3.76,56.59 4.34,56.01 7.44,56.01 7.98,55.47 7.98,54.86 8.36,54.48 10.67,54.48 v1(11.63,55.45) ; v1(120.22,71.83) 119.58,72.47 114.4,72.47 v1(114.4,72.69) ; v1(16.64,55.22) 17.09,55.68 19.51,55.68 21.46,57.63 v1(21.46,58.88) 21.18,59.16 20.45,59.16 v1(19.76,59.84) 19.76,60.58 18.57,61.77 18.57,61.82 v1(17.75,62.64) 18.24,63.12 18.24,64.08 18.8,64.64 ; J15.18 17.7,34.01 17.52,33.82 17.28,33.82 17.16,33.71 16.59,33.71 16.49,33.6 15.54,33.6 14.96,34.19 11.81,34.19 10.69,35.31 v1(10.69,35.76) 10.01,36.45 v1(10.01,37.13) 9.65,37.49 9.65,38.91 v1(9.86,39.12) 9.5,39.47 9.5,40.94 v1(9.86,41.3) 11.05,42.49 12.27,42.49 v1(12.32,42.44) 12.75,42.88 14.41,42.88 C260.1 16.54,44.3 16.54,43.28 16.94,42.88 17.22,42.88 17.48,42.62 v1(17.58,42.62) 17.58,42.32 17.89,42.01 J15.34 ; v1(43.76,10.13) 44.96,11.33 53.92,11.33 54.31,11.71 59.89,11.71 60.15,11.96 v1(60.15,13.08) 60.15,14.3 59.51,14.94 57.84,14.94 57.23,15.54 ; 121.74,71.83 121.74,70.94 v1(122.5,70.18) ; v1(38.94,54.58) 38.94,54.05 35.92,51.03 35.92,46.2 v1(35.76,46.05)
  BOTTOM w0.305: v1(31.32,19.38) 30.99,19.05 J31.6 ; J27.33 40.3,28.5 39.33,29.48 v1(39.2,29.48) ; J15.18 19.56,34.01 19.86,34.31 v1(19.86,34.49) 19.85,34.51 J15.19 ; v1(42.62,32.21) 42.62,31.95 42.17,31.5 J27.21 ; J27.51 40.21,24 39.9,24.31 v1(39.9,24.54) ; v1(17.58,42.62) 17.49,42.71 17.49,43.14 17.85,43.51 J15.37 ; v1(39.98,17.92) 39.98,17.92 40.07,18 J27.75 ; J27.15 v1(42.46,33) ; J15.11 v1(19.63,30.51) ; J27.45 v1(40.03,25.5) ; v1(42.49,34.11) 42.1,34.5 J27.9 ; J27.73 40.17,18.5 40.08,18.59 v1(40,18.59) ; Q13.2 21.62,50.89 v1(21.47,51.03)
  BOTTOM w0.381: J15.22 v1(19.76,36.01) ; 21.59,13.39 20.4,14.58 J2.N4 20.4,16.86 20.19,17.07 ; C33.2 120.73,47.36 ; 120.73,47.36 120.24,46.87 v1(120.24,46.58) ; 120.73,47.36 120.73,46.99 120.98,46.74 v1(120.98,46.58) ; v1(98.25,50.11) 97.67,49.54 C205.1 ; v1(30.96,46.94) v1(31.85,46.05) v1(35.76,46.05) 33.55,43.84 v1(33.55,41.35) 33.29,41.09 C138.1 33.29,39.25 v1(33.48,39.07) ; v1(113.59,49.35) 113.59,48.26 114.31,47.54 Q1.2 114.89,47.07 115.27,46.69 116.54,46.69 116.92,47.07 Q2.2 ; SW2.4 84.56,86.66 v1(83.8,86.66) ; 41.99,36.78 41.42,37.34 J27.G2 43.32,37.6 v1(43.38,37.54) ; R345.1 96.95,55.52 97.33,55.9 v1(97.72,55.9) ; C205.1 97.36,48.72 v1(97.74,48.34) ; C205.1 97.7,49.2 98.73,49.2 v1(98.88,49.35) ; R385.2 17.04,64.9 17.32,64.9 v1(17.5,64.72) ; 107.65,86.18 v1(106.38,86.18) ; 107.65,86.18 SIM1.C5 v1(107.65,84.4) ; 107.65,86.18 v1(107.65,87.96) ; v1(15.24,57.73) D76.8 D76.3 ; v1(32.36,14.06) 32.49,14.19 32.49,14.48 32.49,14.49 J31.8 32.49,17.25 33.1,17.86 v1(33.86,17.86) ; v1(123.15,24.21) 123.15,29.53 v1(122.38,30.3) ; J31.7 27.42,16.68 v1(27.76,16.33) ; v1(83.26,88.21) 83.93,88.21 SW2.2 ; J27.57 42.32,22.5 v1(42.34,22.53) ; v1(13.9,65.08) 14.55,65.08 14.66,65.18 D80.2 ; v1(57.99,70.31) 57.73,70.05 v1(56.21,70.05) 56.06,69.9 54.99,69.9 49.58,64.49 49.02,64.49 48.34,63.8 v1(48.18,63.8) ; v1(19.53,49.05) 19.15,49.05 18.73,49.47 18.73,49.56 C245.1 ; v1(15.32,62.81) 15.21,62.92 D77.8 D77.3 12.93,62.92 v1(12.9,62.89) ; v1(27.37,36.91) v1(27.37,35.42) 27.37,35.29 27.36,35.28 v1(27.36,34.04) ; C185.2 112.57,57.13 v1(112.57,56.44) ; v1(43.13,29.54) 42.67,30 J27.27 ; v1(24.61,64.92) 24.79,64.92 25.76,63.96 C26.1 25.85,63.95 v1(24.97,63.07) ; SW2.1 88.99,88.21 v1(89.74,88.21) ; R33.1 v1(123.01,50.83) ; 120.65,64.24 120.65,65.81 v1(120.29,66.17) ; v1(22.3,45.44) 22.3,46.25 21.85,46.71 J15.42 ; v1(128.73,62.69) v1(128.73,63.7) 128.22,64.21 126.31,64.21 126.31,64.59 127.46,65.74 127.46,67.5 J11.2 126.06,68.89 126.06,72.34 123.39,75.01 122,75.01 v1(121.36,74.37) v1(120.35,74.37) ; v1(19.79,41.88) 19.74,41.88 19.62,42.01 J15.34 ; C206.1 v1(94.5,50.17) ; J27.39 42.34,27 42.71,27.38 42.71,28.49 v1(43.13,28.91) ; v1(96.11,70.08) v1(95.35,70.08) v1(94.59,70.08) ; v1(42.49,35.38) v1(42.49,34.11) ; v1(34.44,50.85) v1(34.44,49.89) ; C203.1 99.85,52.32 v1(100.41,51.77) 100.53,51.89 U22.2 ; v1(32.21,22.43) D48.8 D48.3 ; v1(128.6,55.45) v1(128.6,57.1) 128.6,58.19 v1(128.57,58.22) 128.57,59.99 v1(128.6,60.02) ; R36.1 121.79,47.86 v1(121.79,47.27) ; 58.78,70.31 58.5,70.03 ; J15.31 19.74,40.51 19.76,40.53 v1(19.79,40.53) ; J15.28 v1(19.79,39.01) ; v1(64.39,41.22) 64.81,41.64 C163.1 ; v1(49.86,49.61) v1(50.48,50.23) ; J15.25 v1(19.79,37.51) ; 17.31,33.01 J15.16
  BOTTOM w0.508: R41.1 C35.1 113.87,52.2 v1(114.3,51.77)
  BOTTOM w0.61: J5.H3 132.96,88.72 ; J5.H3 132.29,87.54 ; J5.H3 131.61,88.72 ; H2.1 11.86,51.04 ; H2.1 9.18,48.36 ; H2.1 11.86,45.68 ; 131.51,84.57 J5.H1 ; J5.H1 133.06,84.57 ; J5.H1 132.29,86 ; J5.H4 124.32,88.72 ; J5.H4 122.97,88.72 ; J5.H4 123.65,87.54 ; J5.H2 123.65,86 ; J5.H2 122.87,84.57 ; J5.H2 124.42,84.57 ; J6.22 93.01,84.04 ; J6.22 91.43,82.47 ; J6.22 94.58,82.47 ; J7.4 128.5,3 ; J7.4 126.95,3 ; J7.4 127.72,3.78 ; J7.4 127.72,2.22
  BOTTOM w0.889: J14.23 70.5,88.62 ; J14.23 71.28,87.44 ; J14.23 69.72,87.44 ; J14.23 70.5,86.26 ; 73.74,82.37 73.74,81.48 72.85,81.48 ; 18.11,74.88 19.05,74.88 ; 18.11,74.88 17.17,74.88 ; 18.11,74.88 18.11,73.94 ; 18.11,74.88 18.11,75.82 ; J11.2 127.22,68.51 ; J11.2 126.44,67.74 ; J11.2 126.44,69.29 ; 118.44,9.35 H1.1 ; H1.1 119.96,7.82 ; H1.1 121.49,9.35 ; H1.1 119.96,10.88 ; 132.53,16.71 J24.34 ; J24.34 133.55,17.74 ; J24.34 133.55,15.69 ; J24.33 132.04,16.71 ; J24.33 131.01,15.69 ; J24.33 129.99,16.71 ; J24.33 131.01,17.74 ; J6.19 93.01,78.36 ; J6.19 93.01,75.21 ; J6.19 94.58,76.79 ; 36.91,73.94 36.91,74.88 ; 36.91,74.88 35.97,74.88 ; 36.91,74.88 36.91,75.82 ; 36.91,74.88 37.85,74.88 ; LED1.2 74.63,84.02 ; LED1.2 73.74,84.91 ; LED1.2 72.85,84.02 ; LED1.2 73.74,83.13 ; 4.23,33.48 J16.6 5.89,33.48 ; 90.52,29.93 J27.G4 87.85,27.25 ; 133.55,53.3 J24.6 133.55,51.25 ; 4.23,41.48 J16.14 5.89,41.48 ; 5.89,63 J28.14 4.23,63 ; 121.05,27.25 J27.G3 ; J27.G3 123.72,24.58 ; J27.G3 123.72,29.93 ; 131.01,53.3 J24.5 131.01,51.25 ; 82.2,77.27 J6.13 83.67,77.27 ; 133.55,28.39 J24.24 ; J24.24 133.55,30.44 ; J24.24 132.53,29.41 ; 70.5,83.16 J14.20 69.72,81.48 ; 56,86.26 J14.22 ; J14.22 55.22,87.44 ; J14.22 56.78,87.44 ; J14.22 56,88.62 ; J2.N3 85.2,16.83 ; J2.N3 85.2,13.28 ; J2.N3 83.42,15.05 ; J2.N3 86.98,15.05 ; 6.23,63 J28.13 7.89,63 ; 79.87,84.04 J6.21 78.29,82.47 ; 55.22,81.48 J14.21 ; J14.21 56,83.16 ; J14.21 56.78,81.48
  vias: v1(0.97,20.78) v1(1.09,26.37) v1(6.05,48.72) v1(8.33,48.72) v1(8.86,60.68) v1(8.97,58.52) v1(9.22,57.86) v1(10.21,33.02) v1(10.26,59.51) v1(10.36,27.13) v1(10.49,26.24) v1(10.49,25.22) v1(10.59,57.48) v1(11.07,54.74) v1(11.43,41.1) v1(11.63,38.99) v1(12.4,55.45) v1(12.4,33.22) v1(12.4,32.33) v1(12.78,35.76) v1(13.16,55.45) v1(13.28,33.22) v1(13.54,51.89) v1(13.67,40.67) v1(14.17,33.22) v1(14.43,32.33) v1(14.55,51.89) v1(14.81,23.95) v1(14.81,22.3) v1(14.81,20.52) v1(15.44,22.3) v1(15.44,20.52) v1(15.95,55.47) v1(16.08,54.79) v1(17.09,27.33) v1(17.09,26.75) v1(17.07,26.14) v1(17.07,25.53) v1(17.7,59.82) v1(17.78,72.85) v1(17.75,72.19) v1(17.78,71.5) v1(17.81,70.92) v1(17.86,69.11) v1(17.88,68.4) v1(18.06,58.52) v1(19.38,19.89) v1(19.84,57.96) v1(20.12,49.07) v1(20.14,20.02) v1(20.37,69.42) v1(20.9,19.89) v1(21.79,65.74) v1(21.89,75.92) v1(21.84,64.62) v1(23.77,54.71) v1(24.49,75.92) v1(24.71,65.48) v1(25.22,67.26) v1(25.63,50.98) v1(25.6,1.09) v1(26.11,67.26) v1(27.58,12.75) v1(27.89,13.23) v1(28.02,25.22) v1(28.45,12.24) v1(28.65,25.22) v1(28.91,48.9) v1(29.29,73.53) v1(30.71,25.35) v1(30.71,24.71) v1(30.94,58.75) v1(31.19,1.09) v1(31.32,15.42) v1(31.6,11.58) v1(31.95,59.51) v1(32.23,76) v1(32.92,58.09) v1(32.97,83.9) v1(33.38,76.3) v1(33.55,8.99) v1(33.73,21.41) v1(33.73,20.78) v1(34.16,47.88) v1(34.24,9.73) v1(34.49,76.02) v1(34.49,46.69) v1(34.57,40.21) v1(35.76,41.35) v1(35.76,39.07) v1(36.78,1.09) v1(38.23,69.82) v1(38.56,37.54) v1(39.19,13.79) v1(40.77,75.84) v1(41.66,69.39) v1(42.11,1.09) v1(42.3,17.86) v1(42.49,25.76) v1(43.13,64.97) v1(43.13,16.97) v1(43.26,24.21) v1(43.46,32.08) v1(43.76,67.16) v1(43.89,24.54) v1(44.4,64.97) v1(44.42,62.92) v1(44.53,17.09) v1(44.7,29.54) v1(44.7,28.91) v1(45.16,68.35) v1(45.34,75.84) v1(45.62,63.07) v1(46.15,64.97) v1(46.81,63.91) v1(47.57,1.09) v1(47.93,14.71) v1(48.41,73.51) v1(49.63,75.46) v1(49.86,11.51) v1(50.93,74.37) v1(51.38,11.51) v1(51.64,75.39) v1(53.04,37.77) v1(53.54,26.11) v1(54.18,28.65) v1(54.18,26.11) v1(54.56,1.09) v1(54.69,88.98) v1(54.69,19) v1(55.09,16.76) v1(55.45,19) v1(55.83,28.63) v1(55.96,26.11) v1(56.36,66.32) v1(57.33,19) v1(58.09,74.75) v1(58.14,63.32) v1(58.34,78.79) v1(58.72,16.81) v1(58.75,63.32) v1(58.75,41.35) v1(59.36,63.32) v1(59.89,84.28) v1(59.97,73.28) v1(59.97,63.32) v1(60.02,40.08) v1(60.4,88.98) v1(60.35,17.35) v1(60.55,26.14) v1(60.96,19.25) v1(61.04,1.09) v1(61.16,26.14) v1(61.29,41.35) v1(61.29,38.81) v1(61.47,78.79) v1(61.44,73.23) v1(62.43,63.32) v1(62.81,19.25) v1(62.84,63.78) v1(63.45,86.18) v1(63.58,19.25) v1(64.69,75.41) v1(65.89,26.11) v1(65.99,84.28) v1(66.37,88.85) v1(66.37,1.09) v1(66.47,26.11) v1(66.62,64.8) v1(66.9,19.2) v1(67.39,9.22) v1(67.89,19.23) v1(68.45,14.81) v1(68.78,19.25) v1(69.8,27.58) v1(69.75,9.27) v1(71.73,11.4) v1(71.7,1.09) v1(72.47,83.01) v1(72.97,88.85) v1(74.3,1.09) v1(74.5,75.77) v1(74.5,40.03) v1(74.98,6.63) v1(75.44,42.55) v1(75.77,86.31) v1(76.53,46.33) v1(77.34,7.39) v1(77.55,1.09) v1(78.77,7.49) v1(78.97,36.35) v1(79.71,84.53) v1(79.71,6.55) v1(79.83,88.98) v1(79.83,47.22) v1(81,54.56) v1(80.95,51.56) v1(81.69,7.49) v1(83.9,11.51) v1(84.4,6.43) v1(84.91,84.66) v1(84.89,54.53) v1(85.42,1.09) v1(85.67,49.1) v1(85.75,7.34) v1(86.56,49.86) v1(86.94,72.97) v1(87.07,25.48) v1(87.17,73.66) v1(87.33,17.17) v1(87.58,23.7) v1(88.21,23.7) v1(88.24,33.96) v1(88.49,7.24) v1(89.36,6.43) v1(89.51,34.54) v1(90.25,1.09) v1(90.83,17.98) v1(90.88,88.98) v1(90.88,84.53) v1(92.41,78.69) v1(92.79,73.48) v1(92.91,86.94) v1(93.01,72.64) v1(92.96,64.47) v1(93.42,73.48) v1(93.55,0.99) v1(94.7,27.14) v1(96.47,20.09) v1(97.49,84.53) v1(97.49,81.1) v1(97.61,88.98) v1(98.58,66.5) v1(98.58,14.83) v1(98.63,9.96) v1(98.88,56.46) v1(98.88,50.11) v1(99.01,11.23) v1(98.96,10.62) v1(99.14,9.47) v1(99.26,66.5) v1(99.64,0.99) v1(99.95,66.5) v1(100.41,82.63) v1(100.63,66.5) v1(100.69,56.46) v1(101.17,78.18) v1(101.32,66.47) v1(101.42,49.1) v1(101.98,28.19) v1(102.34,72.57) v1(102.57,56.46) v1(102.82,88.98) v1(102.82,84.53) v1(102.82,81.23) v1(102.74,22.81) v1(102.95,20.27) v1(102.95,17.35) v1(102.95,14.94) v1(103.28,58.19) v1(103.68,50.67) v1(103.91,27.18) v1(103.96,26.26) v1(104.09,0.99) v1(104.34,14.68) v1(104.98,56.46) v1(105.36,48.34) v1(105.61,17.48) v1(105.66,22.91) v1(105.82,56.44) v1(105.74,20.27) v1(105.87,83.01) v1(105.99,8.2) v1(106.38,16.76) v1(106.63,56.44) v1(106.76,14.68) v1(106.76,8.2) v1(107.52,11.51) v1(107.62,55.04) v1(107.65,88.98) v1(107.65,8.2) v1(107.77,36.75) v1(107.85,42.75) v1(108.28,22.89) v1(108.28,20.27) v1(108.41,17.48) v1(108.41,14.68) v1(108.43,0.99) v1(108.92,81.1) v1(108.99,66.67) v1(109.55,66.75) v1(109.73,67.41) v1(110.31,67.51) v1(110.44,64.97) v1(110.44,15.32) v1(110.54,22.81) v1(110.57,20.27) v1(110.57,17.48) v1(111.23,8.69) v1(111.2,8.08) v1(111.3,15.32) v1(111.3,14.68) v1(111.46,15.95) v1(111.58,34.11) v1(111.56,14.05) v1(111.68,27.33) v1(112.01,60.33) v1(111.96,54.03) v1(112.32,8.69) v1(112.34,88.98) v1(112.34,13.54) v1(112.7,11.76) v1(112.78,26.01) v1(112.8,0.99) v1(112.85,46.05) v1(112.85,35.26) v1(113.18,49.76) v1(113.36,13.79) v1(113.87,19.99) v1(113.87,19.41) v1(114.02,83.19) v1(114.12,13.79) v1(114.17,56.82) v1(114.38,84.66) v1(114.38,81.1) v1(114.76,16.59) v1(114.78,11.76) v1(114.88,13.79) v1(115.39,12.8) v1(115.52,56.26) v1(115.49,19.99) v1(115.49,19.41) v1(115.77,13.79) v1(115.87,10.62) v1(116.28,16.21) v1(116.66,13.79) v1(116.66,12.24) v1(116.79,7.06) v1(116.97,19.99) v1(116.97,19.41) v1(117.04,17.35) v1(117.42,0.99) v1(117.53,13.79) v1(117.93,16.59) v1(118.06,84.02) v1(118.06,28.65) v1(118.41,13.79) v1(118.41,12.47) v1(118.82,21.92) v1(118.82,17.35) v1(119.08,88.98) v1(119.2,13.64) v1(119.33,25.48) v1(119.33,16.33) v1(119.46,21.92) v1(119.71,16.97) v1(119.71,13.16) v1(119.84,21.16) v1(120.09,12.52) v1(120.35,17.48) v1(120.85,12.52) v1(120.98,55.96) v1(121.62,55.96) v1(121.62,12.52) v1(121.95,56.49) v1(121.95,18.69) v1(122.07,0.99) v1(122.25,88.98) v1(122.25,55.96) v1(122.25,55.32) v1(122.25,54.69) v1(122.43,18.19) v1(122.38,12.52) v1(122.5,85.17) v1(122.5,83.9) v1(122.76,45.97) v1(123.14,13.79) v1(123.14,13.03) v1(123.16,12.34) v1(123.27,70.82) v1(123.27,70.18) v1(123.55,14.27) v1(124.46,75.82) v1(125.17,78.54) v1(125.65,1.02) v1(125.81,88.98) v1(126.06,85.42) v1(126.09,44.93) v1(126.06,4.9) v1(126.31,82.83) v1(126.82,85.42) v1(126.92,19.05) v1(126.85,18.19) v1(127.2,20.78) v1(127.56,68.91) v1(127.84,79.48) v1(127.97,86.31) v1(128.4,82.88) v1(128.47,67.01) v1(128.93,37.97) v1(128.98,85.29) v1(129.29,46.81) v1(129.49,45.42) v1(129.46,16.23) v1(129.59,16.97) v1(129.62,4.9) v1(129.62,1.09) v1(129.74,88.98) v1(130.2,40.92) v1(132.28,37.87) v1(132.28,33.25) v1(132.26,25.6) v1(132.28,22.63) v1(133.02,51.13) v1(133.2,79.68) v1(133.5,70.59) v1(133.81,88.98) v1(133.81,5.03) v1(133.93,85.67) v1(133.93,81.48) v1(133.93,68.02) v1(133.93,63.7) v1(133.93,59.64) v1(133.93,12.27) v1(133.93,9.6) v1(134.39,77.47) v1(134.39,72.87) v2(49.35,53.57) v2(78.16,71.04) v2(80.92,71.4) v2(82.12,74.24) v2(82.22,71.58) v2(83.49,74.42) v2(86.66,74.85) v2(87.58,70.41) v2(89.74,70.38)
